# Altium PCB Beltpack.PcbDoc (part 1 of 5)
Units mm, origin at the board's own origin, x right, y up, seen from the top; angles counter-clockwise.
Board outline 85 x 81 mm, 4 copper layers (Top Layer, Inner-1, Inner_GND, Bottom Layer), stack 1.556 mm thick; 389 components, 291 nets, 1372 pads, 660 vias.
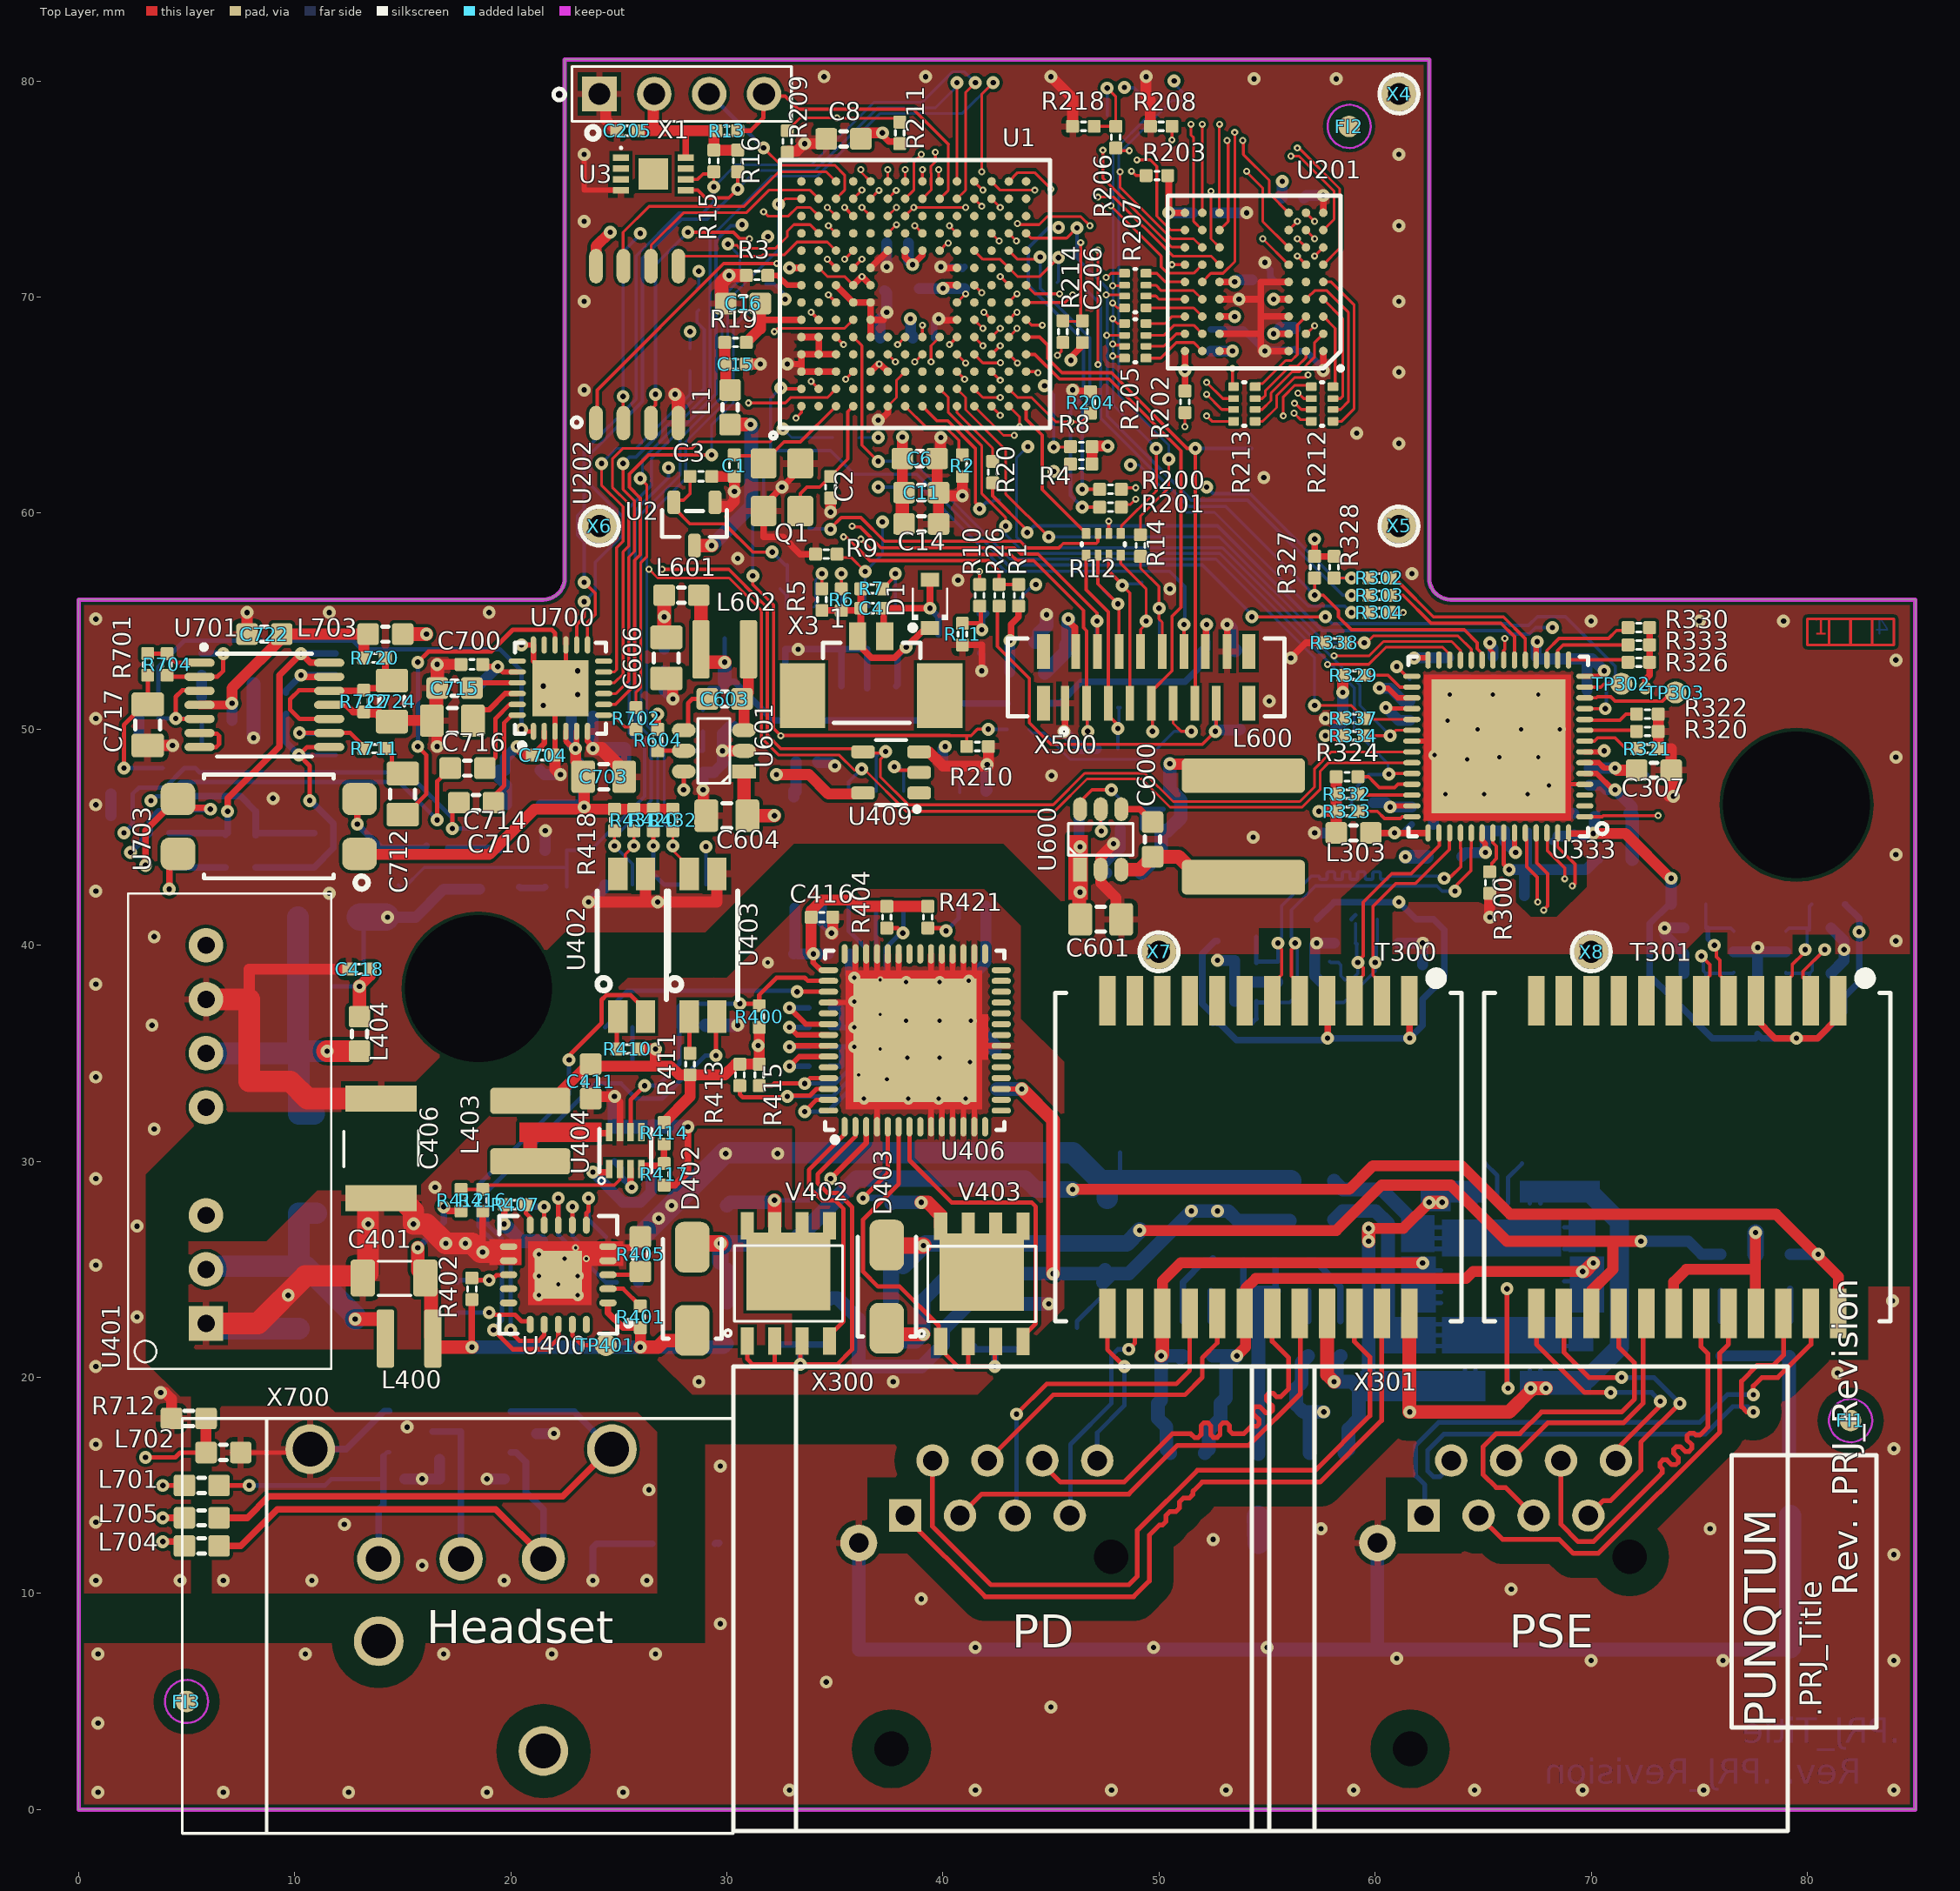
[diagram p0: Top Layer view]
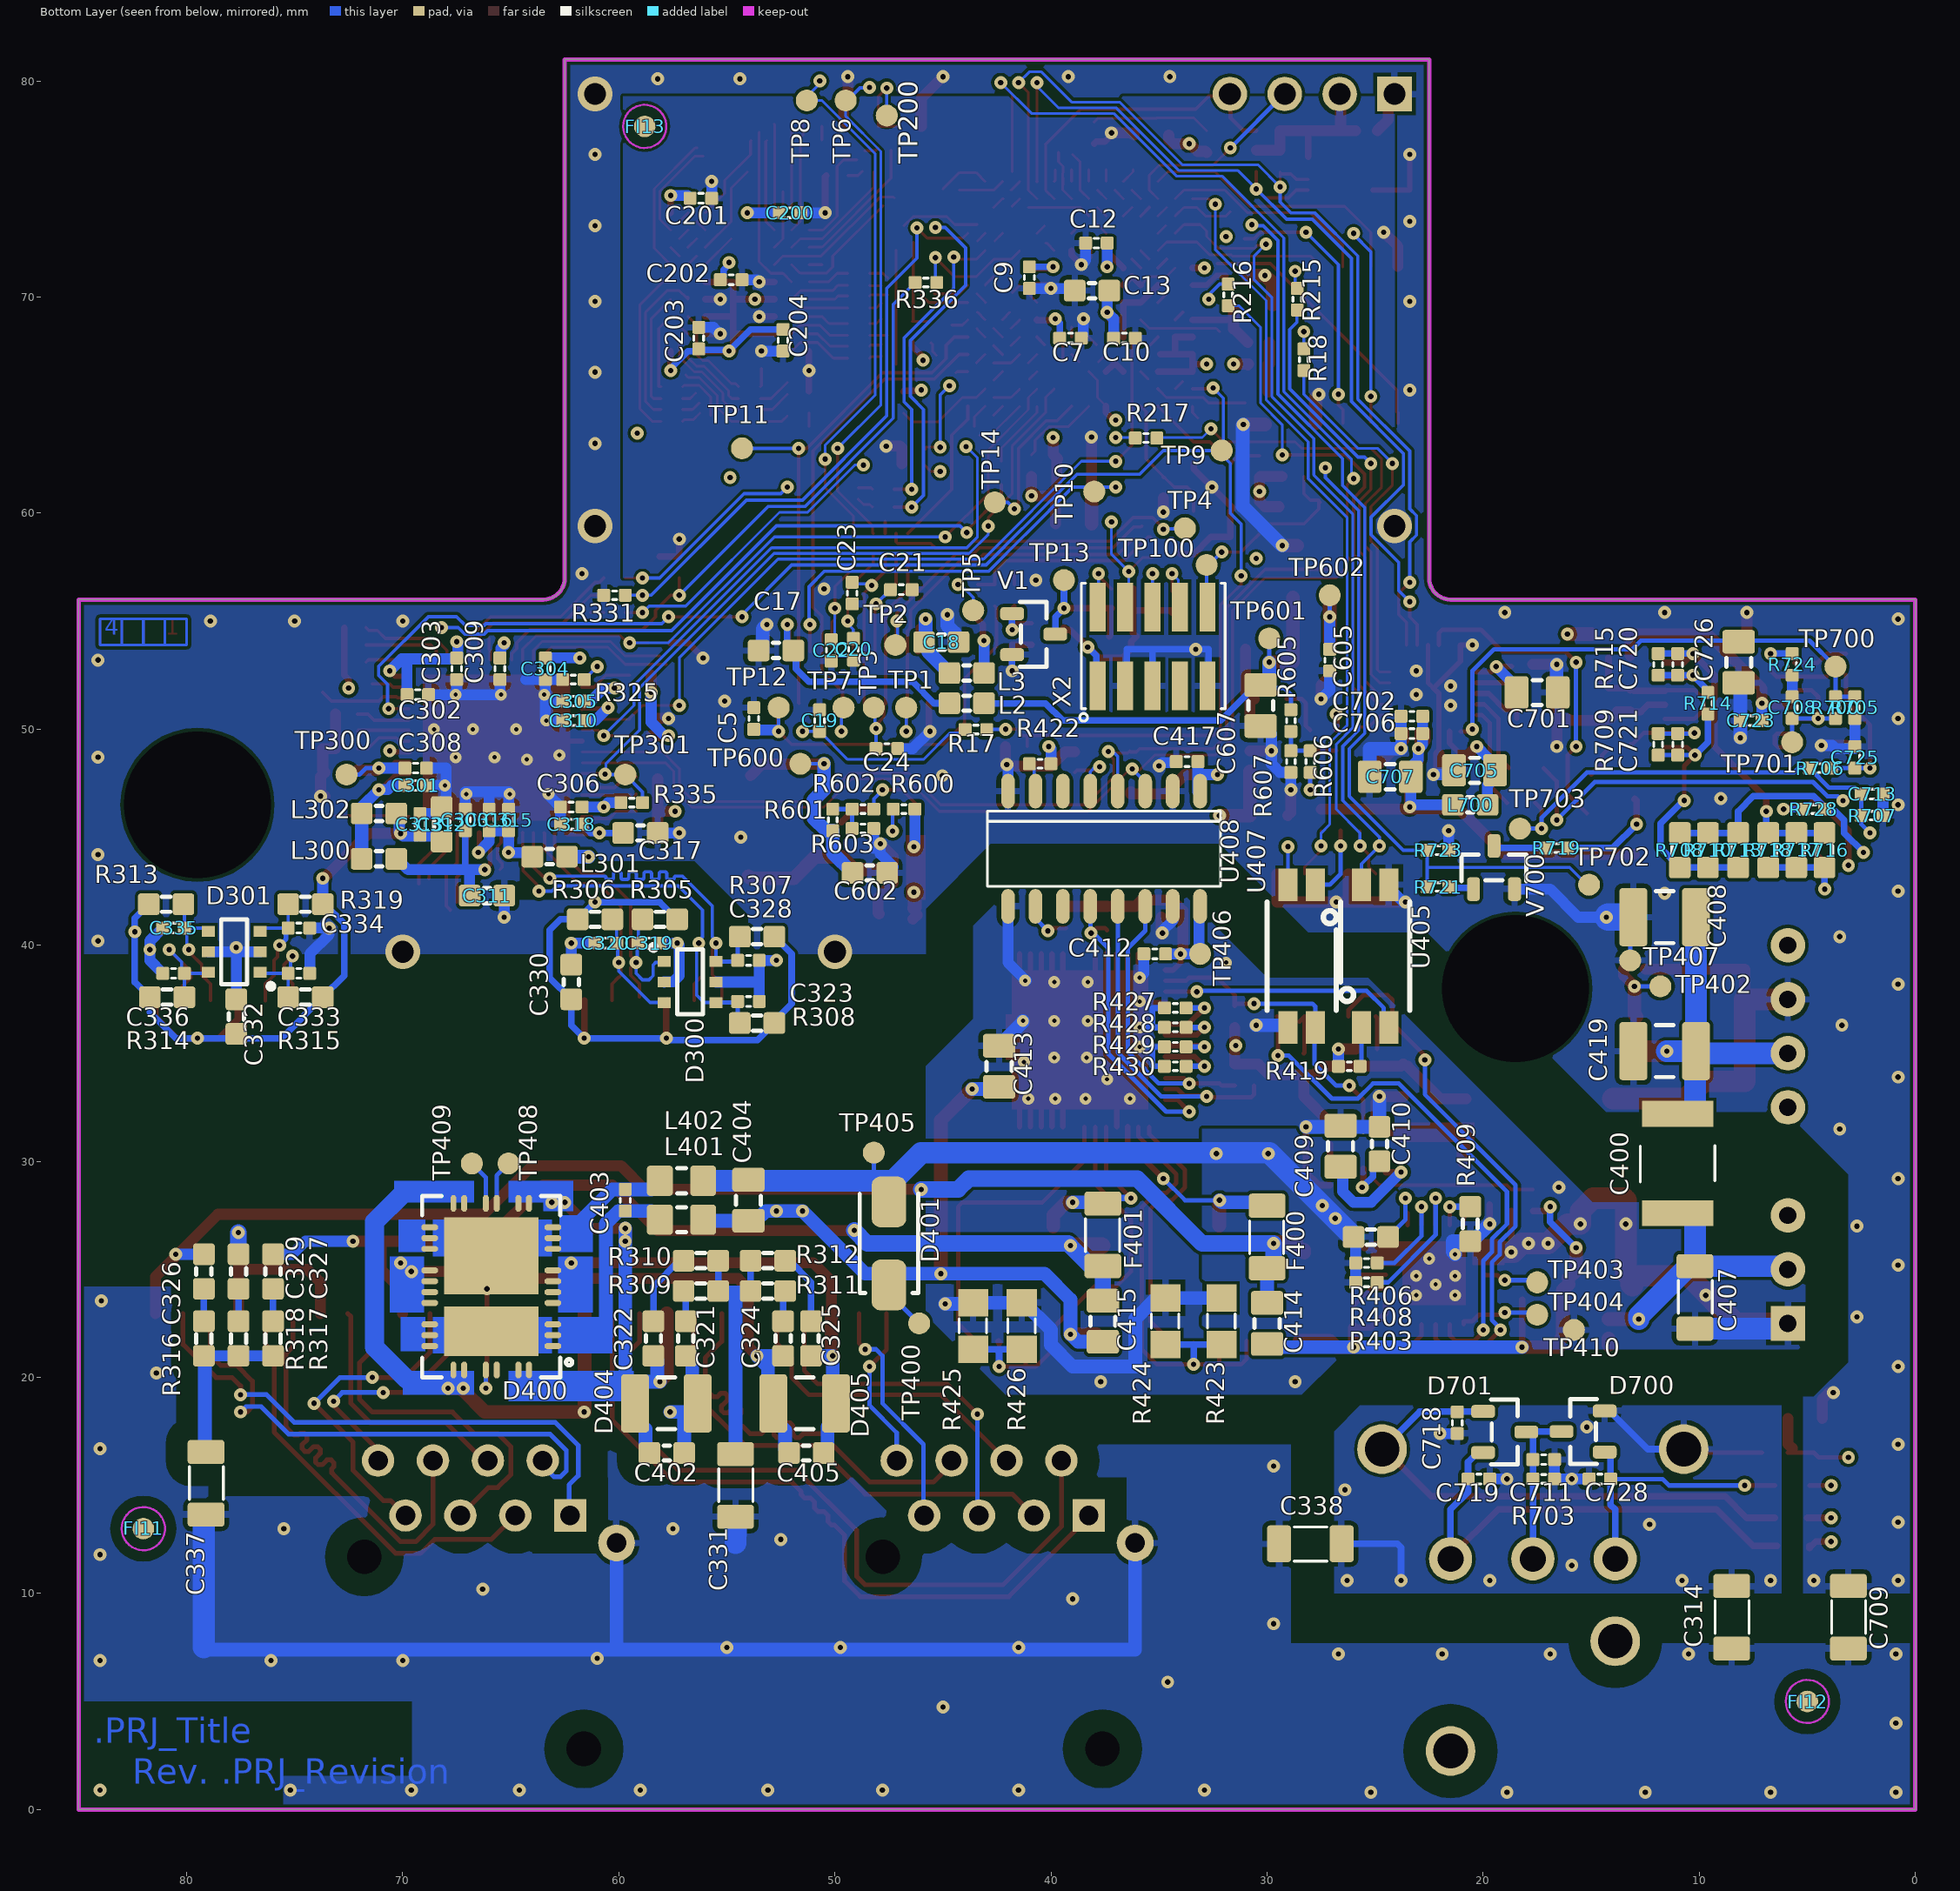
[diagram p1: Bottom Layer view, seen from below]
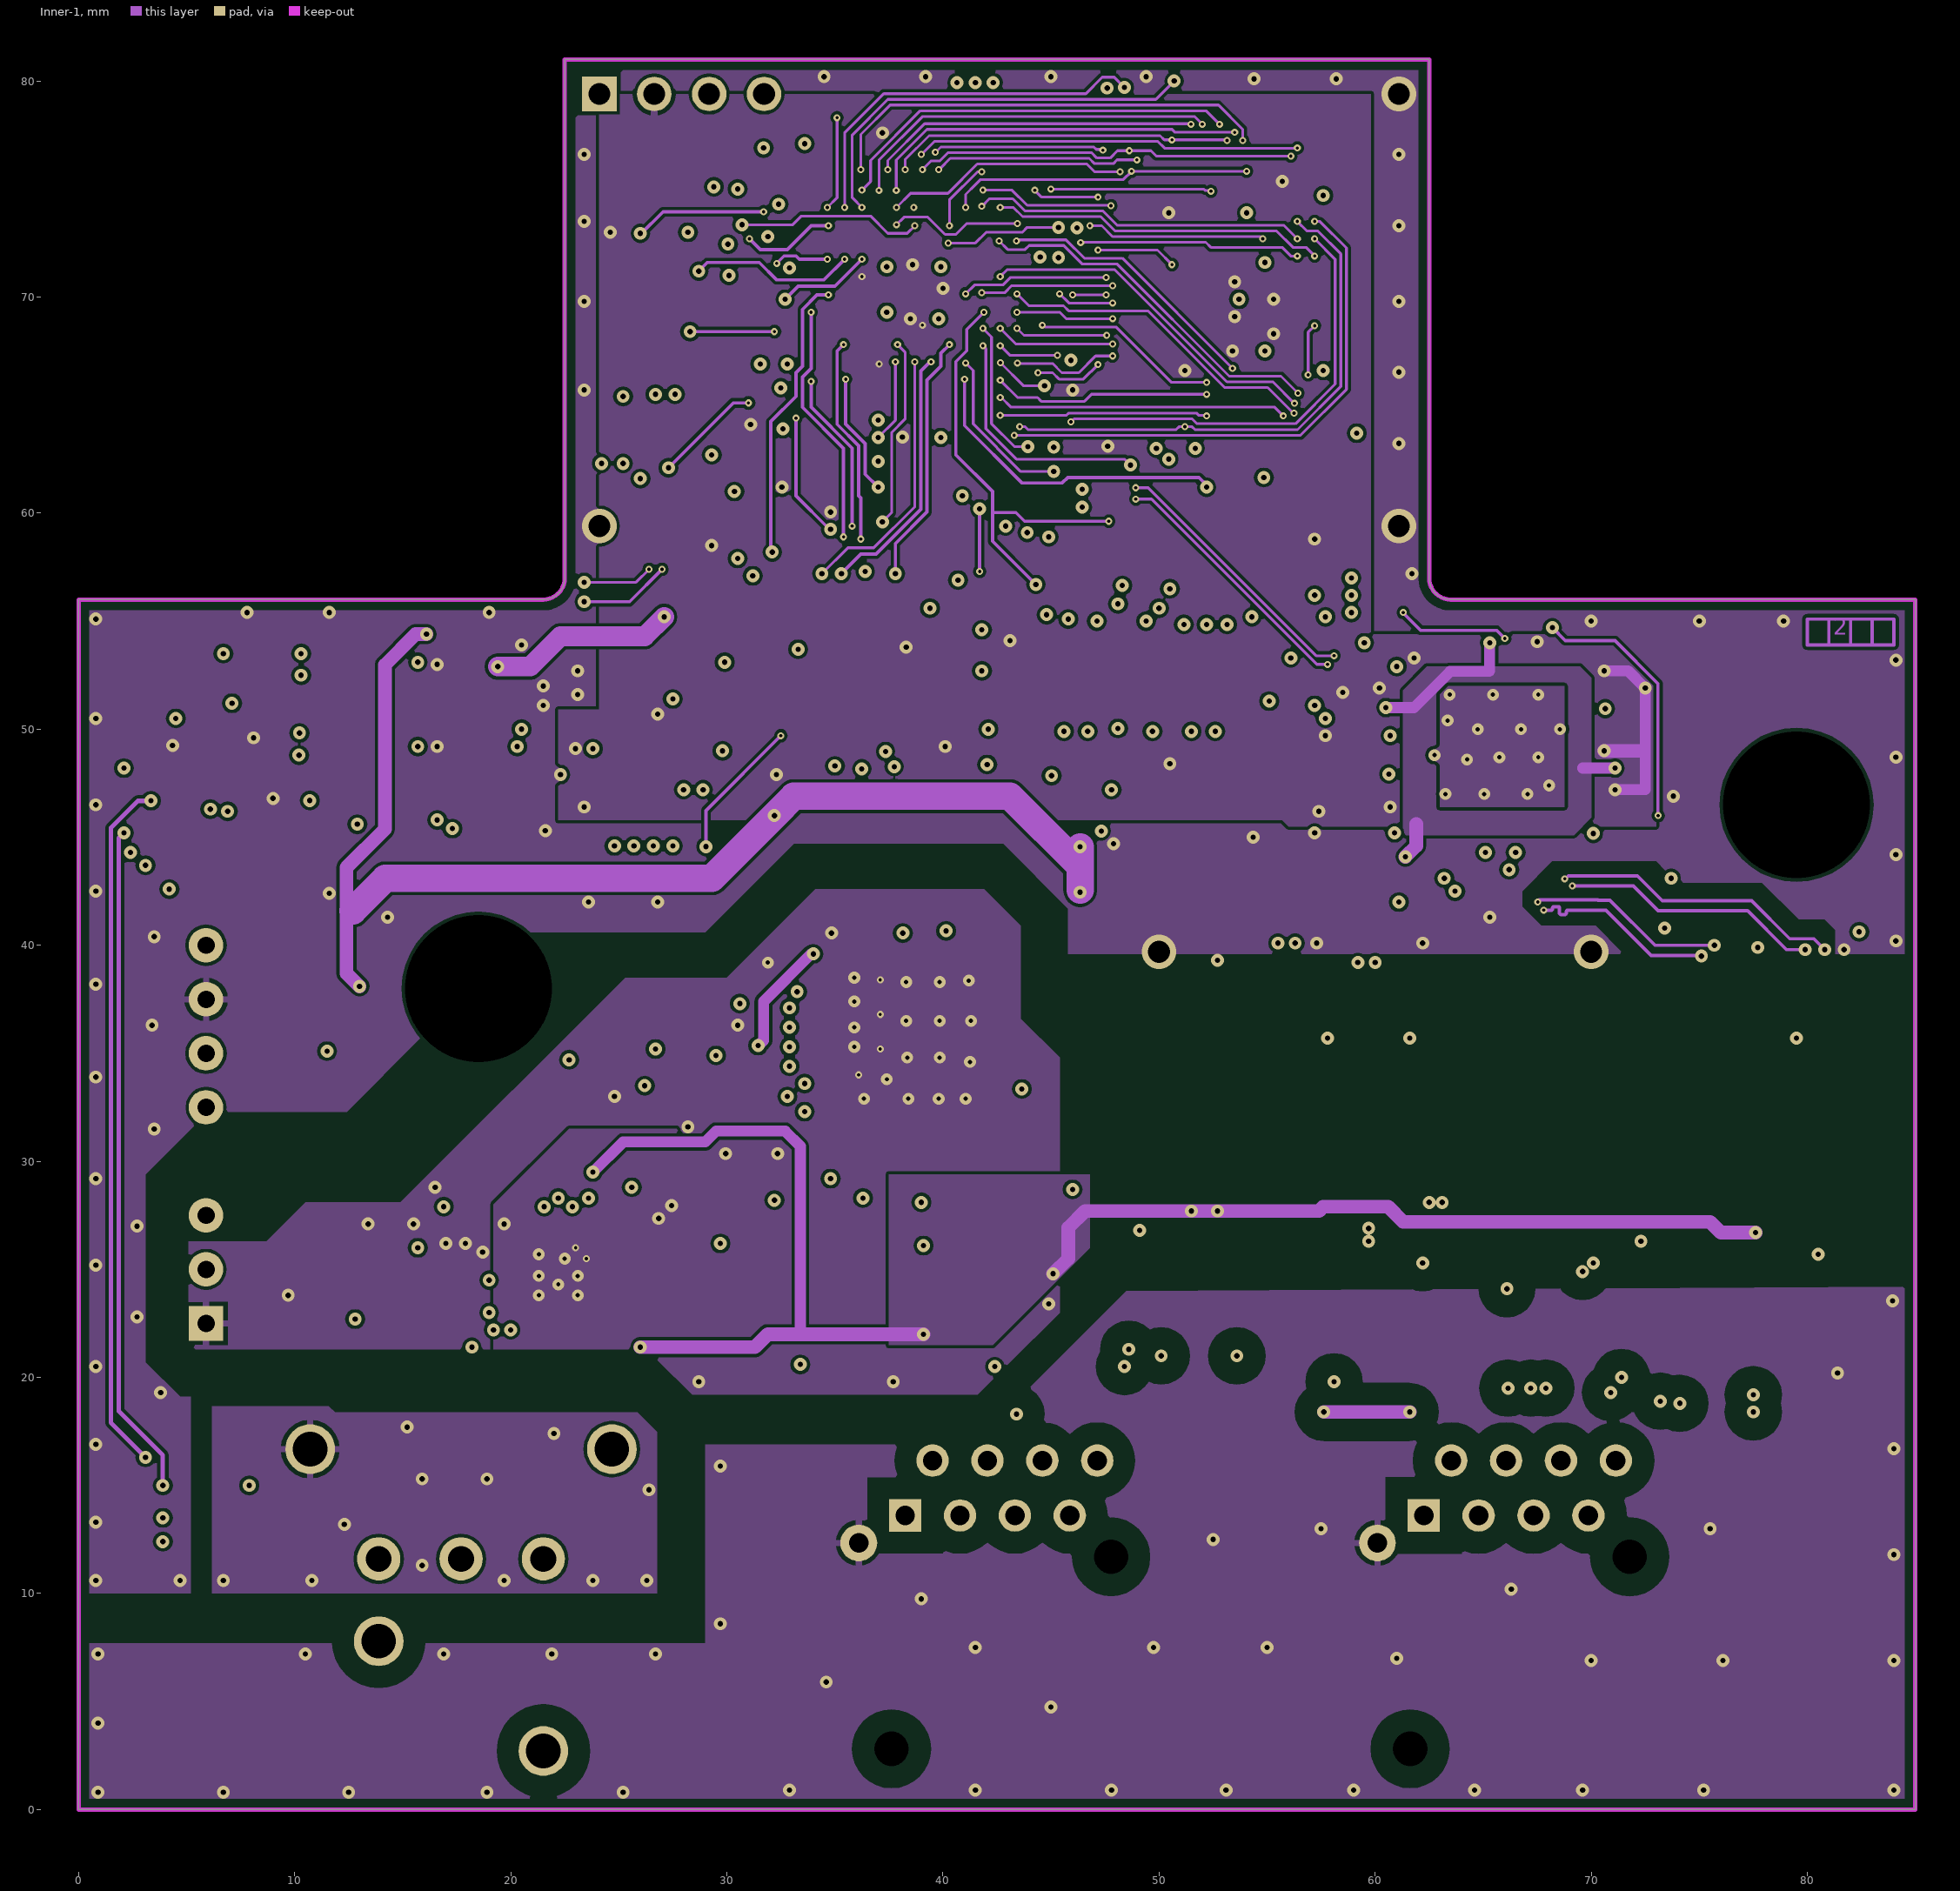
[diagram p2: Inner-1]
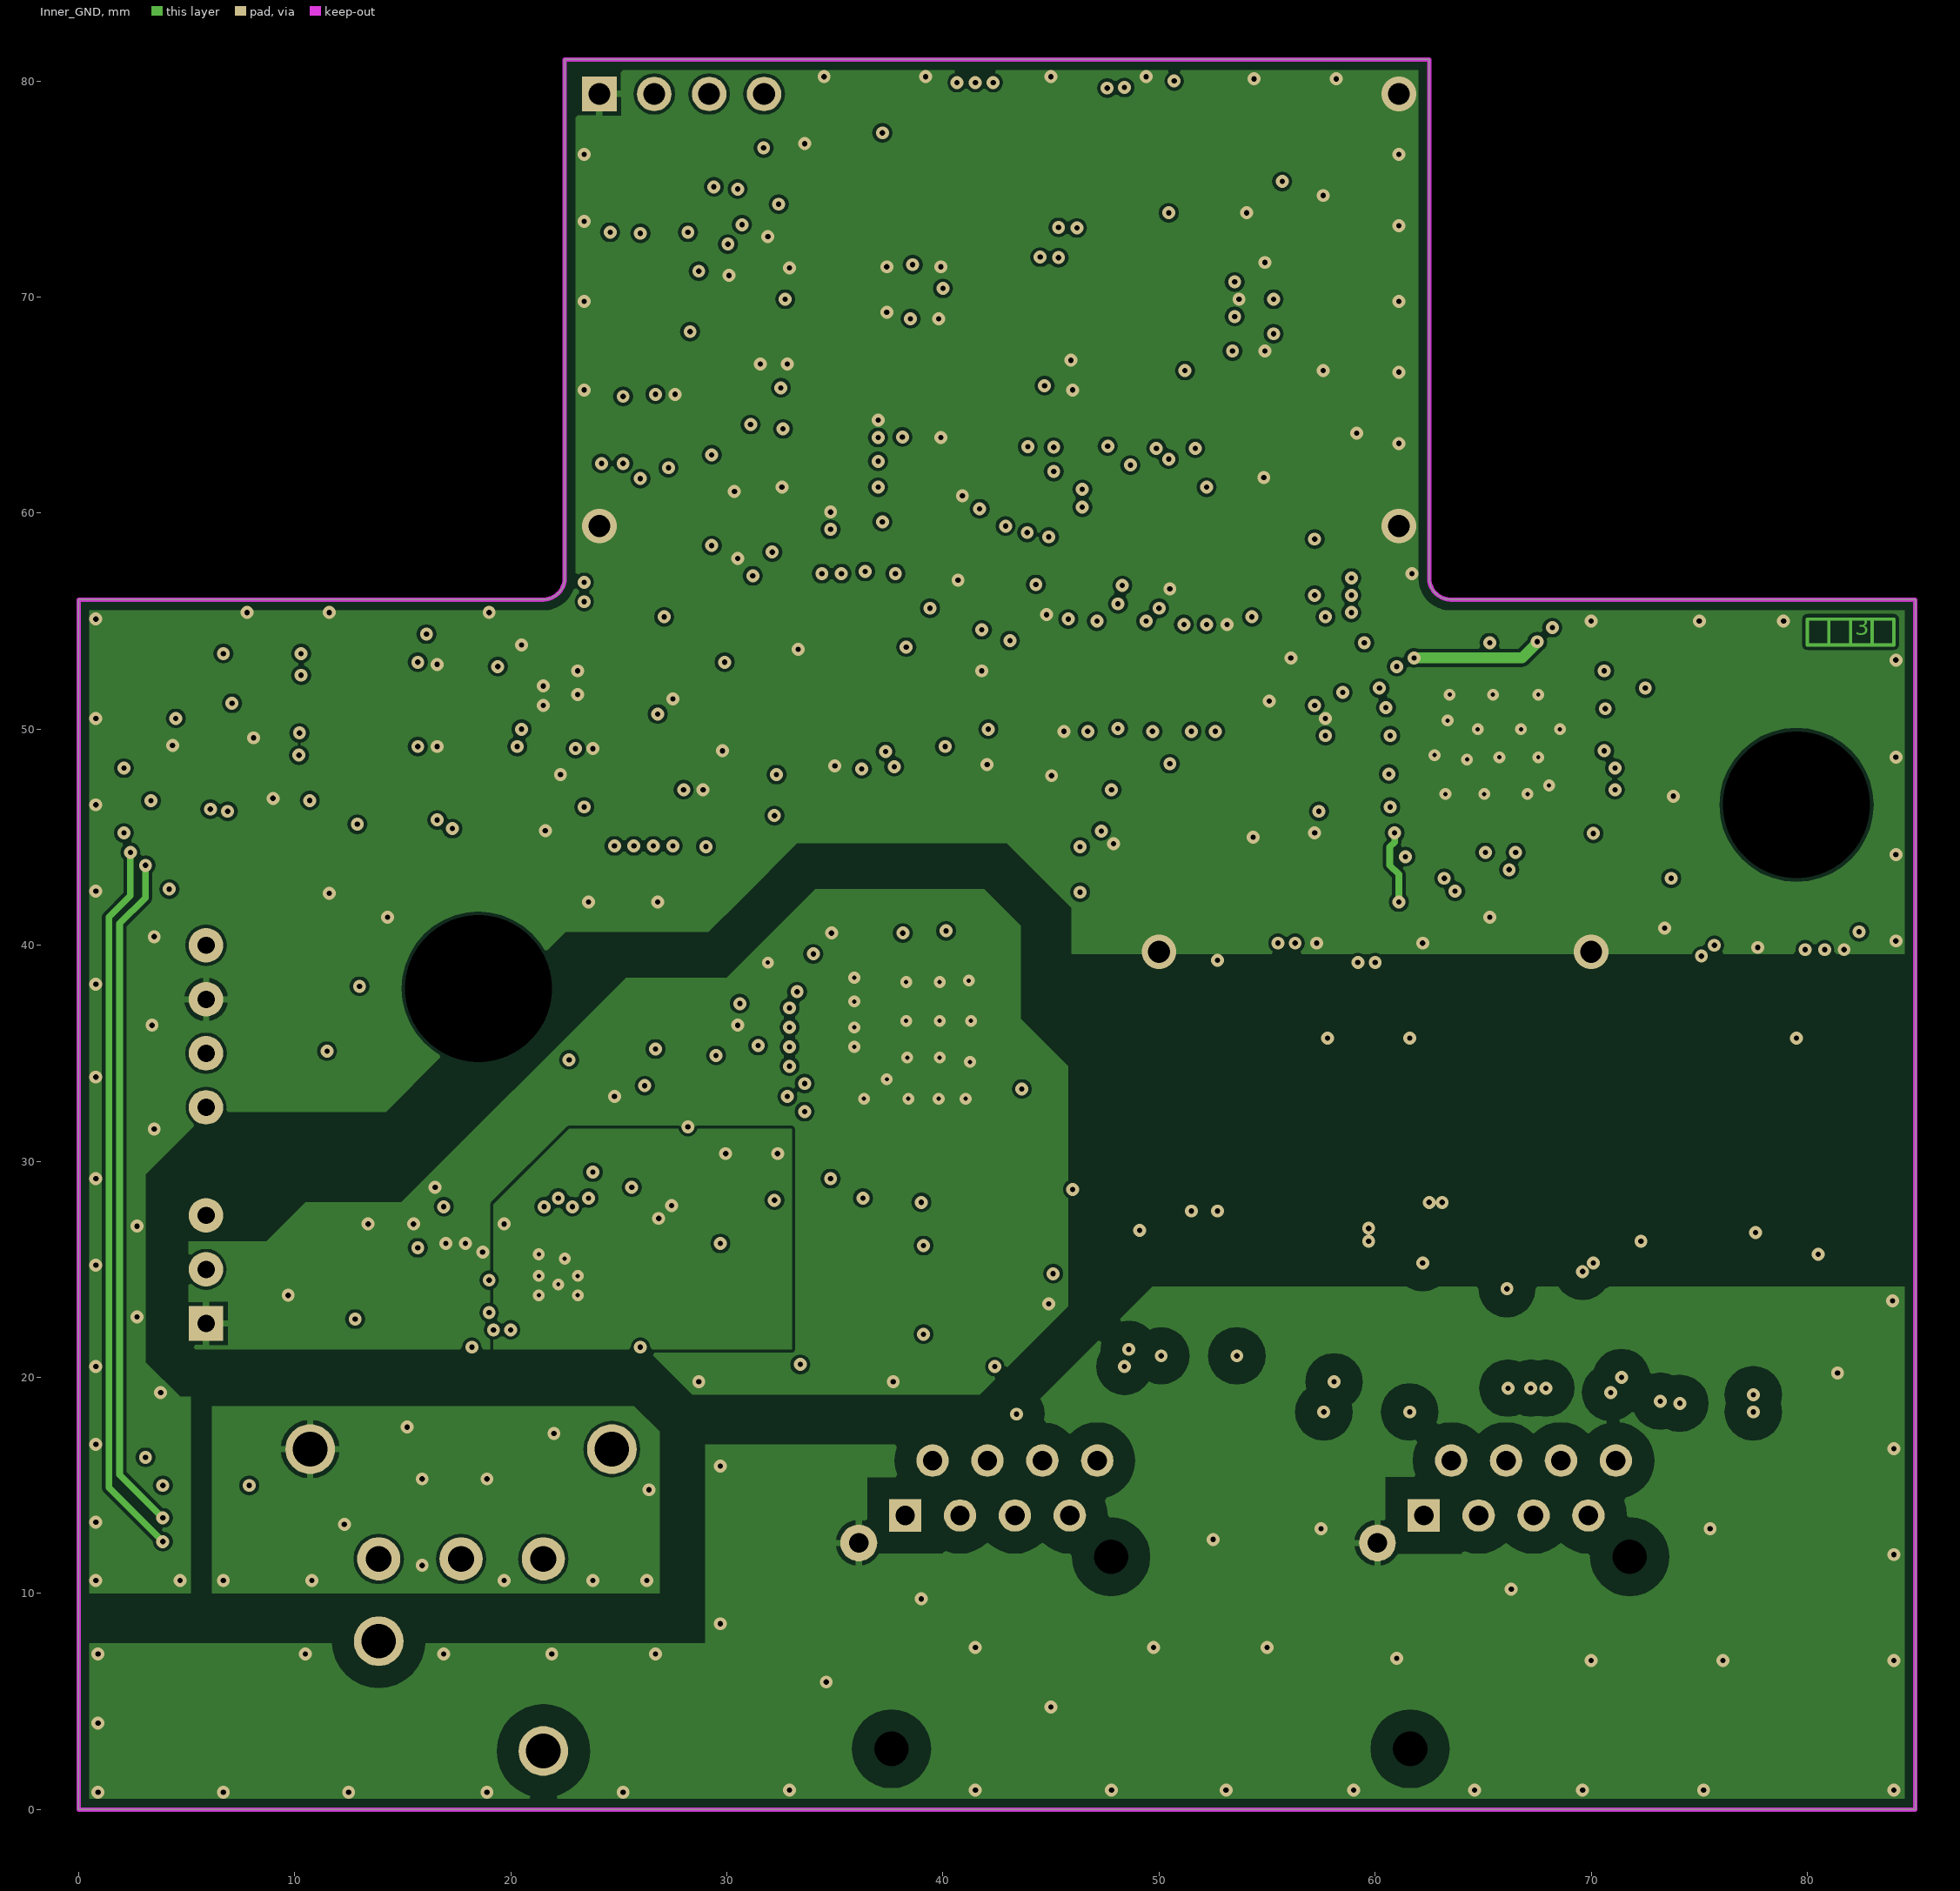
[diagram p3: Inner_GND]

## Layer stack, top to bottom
Top Solder: solder mask 0.017, Solder Resist, Dk 3.3
Top Layer: signal copper 0.035
Dielectric1: core 0.108, Dk 3.6
Inner-1: signal copper 0.035
Dielectric2: prepreg 1.2, FR-4, Dk 4.2
Inner_GND: signal copper 0.035
Dielectric 3: core 0.108, Dk 3.6
Bottom Layer: signal copper 0.035
Bottom Solder: solder mask 0.017, Solder Resist, Dk 3.3

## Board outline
0,0 0,56 21.5,56 ccw(c21.5,57) 22.5,57 22.5,81 62.5,81 62.5,57 ccw(c63.5,57) 63.5,56 85,56 85,0

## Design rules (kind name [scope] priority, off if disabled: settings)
AssemblyTestpoint [All] p1: testpointundercomponent=TRUE minsize=1 maxsize=2.54 preferedsize=1 minholesize=0 maxholesize=1 preferedholesize=0 testpointgrid=0.025 usegrid=FALSE gridtolerance=0 allowsidebottom=TRUE minspacing=2
BoardOutlineClearance BoardClearanceINNER [OnLayer('Inner-1')   OR OnLayer ('Inner_GND')] p1: gap=0.5 ignorepadtopadclearanceinfootprint=FALSE
Clearance Clearance_3V3MCU_TOP [InNamedPolygon('L4_3V3MCU')] p1: gap=0.127 ignorepadtopadclearanceinfootprint=FALSE except(0: Arc-Hole Track-Hole SMDPad-Hole THPad-Hole Via-Hole Fill-Hole Poly-Hole Region-Hole Text-Hole)
Clearance Clearance_GND_MCUTOP [InNamedPolygon('GND_MCUTOP')] p2: gap=0.15 ignorepadtopadclearanceinfootprint=FALSE
Clearance Clearance_3V3INNER [InNamedPolygon('3V3_INNER')] p3: gap=0.15 ignorepadtopadclearanceinfootprint=FALSE
Clearance Clearance_Earth [InNet('EARTH') vs Not IsBoardOutline And Not IsKeepOut] p4: gap=1.016 ignorepadtopadclearanceinfootprint=TRUE // Bob Smith plane
Clearance Clearance_Polygon [InPolygon] p5: gap=0.15 ignorepadtopadclearanceinfootprint=FALSE
Clearance Clearance_SolderPad [(InPadClass('Pad Class BoardEdge')) vs (IsBoardCutoutRegion)] p6: gap=0.508 ignorepadtopadclearanceinfootprint=FALSE except(0: Arc-Hole Track-Hole SMDPad-Hole THPad-Hole Via-Hole Fill-Hole Poly-Hole Region-Hole Text-Hole)
Clearance Clearance_DiffPair [(InDifferentialPairClass('All Differential Pairs'))] p7: gap=0.102 ignorepadtopadclearanceinfootprint=FALSE
Clearance [All] p8: gap=0.135 ignorepadtopadclearanceinfootprint=FALSE
ComponentClearance [All] p1: gap=0.2 collisioncheckmode=3 verticalgap=0.2 showdistances=FALSE
DiffPairsRouting ETH_Routing [All] p1: maxlimit=0.508 minlimit=0.152 mostfreqgap=0.305 toplayer_minwidth=0.127 toplayer_maxwidth=0.305 toplayer_prefwidth=0.152 midlayer1_minwidth=0.127 midlayer1_maxwidth=0.305 midlayer1_prefwidth=0.152 midlayer2_minwidth=0.127 midlayer2_maxwidth=0.305 midlayer2_prefwidth=0.152 bottomlayer_minwidth=0.127 bottomlayer_maxwidth=0.305 bottomlayer_prefwidth=0.152 maxuncoupledlength=12.7 // 100 Ohm diff pair (acc. to WE)
FabricationTestPointUsage TestPointUsage [All] p1: valid=0 allowmultiple=FALSE
FabricationTestpoint Testpoint [All] p1: side=3 testpointundercomponent=TRUE minsize=1 maxsize=2.54 preferedsize=1.524 minholesize=0 maxholesize=1 preferedholesize=0.813 testpointgrid=0.025 allowsidetop=TRUE allowsidebottom=TRUE usegrid=FALSE gridtolerance=0
HoleSize HoleSize_BigPad [(InPadClass('PadBig'))] p1: absolutevalues=TRUE maxlimit=25.4 minlimit=0.025 maxpercent=80.000 minpercent=20.000
HoleSize HoleSize_RJ45_Mountighole [(InPadClass('PAD_HOLE'))] p2: absolutevalues=FALSE maxlimit=0 minlimit=0 maxpercent=80.000 minpercent=-20.000
HoleSize [All] p3: absolutevalues=TRUE maxlimit=3.81 minlimit=0.15 maxpercent=80.000 minpercent=20.000
MinimumSolderMaskSliver [All] p1: minsoldermaskwidth=0.3
PlaneClearance [All] p1: clearance=0.203
PlaneConnect [All] p1: planeconnectstyle=Relief reliefexpansion=0.152 reliefentries=4 reliefconductorwidth=0.254 reliefairgap=0.152
PolygonConnect PolygonConnect_3V3_INNER [All vs IsNamedPolygon('3V3_INNER')] p1: connectstyle=Direct reliefconductorwidth=0.254 reliefentries=4 polygonreliefangle="90 Angle" airgapwidth=0.254
PolygonConnect PolygonConnect_Via [IsVia] p2: connectstyle=Direct reliefconductorwidth=0.254 reliefentries=4 polygonreliefangle="90 Angle" airgapwidth=0.254
PolygonConnect [All] p3: connectstyle=Relief reliefconductorwidth=0.305 reliefentries=4 polygonreliefangle="90 Angle" airgapwidth=0.203
RoutingVias [All] p1: holewidth=0.25 width=0.6 viastyle="Through Hole" minholewidth=0.15 minwidth=0.325 maxholewidth=0.711 maxwidth=1.27
SilkToSolderMaskClearance SilkscreenOverComponentPads [IsPad] p1: minsilkscreentomaskgap=0.254 clearancetoexposedcopper=TRUE
SolderMaskExpansion [All] p1: expansion=0
Width [All] p1: maxlimit=2.54 minlimit=0.127 preferedwidth=0.152 midlayer2_minwidth=0.152 minimp=50.000000 maximp=50.000000 favimp=50.000000
20 further rules are at their usual default settings.

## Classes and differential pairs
pad class PadBig: Free-HOLE1 Free-HOLE2
differential pair ETHOUT_T2: +ETHOUT_T2_P -ETHOUT_T2_N
differential pair ETHOUT_T1: +ETHOUT_T1_P -ETHOUT_T1_N
differential pair ETHIN_T2: +ETHIN_T2_P -ETHIN_T2_N
differential pair ETHIN_T1: +ETHIN_T1_P -ETHIN_T1_N
differential pair RXA: +RXA_P -RXA_N
differential pair RXB: +RXB_P -RXB_N
differential pair TXA: +TXA_P -TXA_N
differential pair TXB: +TXB_P -TXB_N

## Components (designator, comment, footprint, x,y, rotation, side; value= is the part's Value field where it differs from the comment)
C1 "15P" C0402 30.35,62.2 r270 top
C2 "15P" C0402 34.8,61.2 r270 top
C3 "220P" C0402 28.8,61.7 r180 top
C4 "100N" C0402 36.7,55.6 r0 top
C5 "220P" C0402 53.75,50.493 r270 bottom
C6 "4.7N" C0603 38.925,62.525 r0 top
C7 "100N" C0402 39.1,68.1 r0 bottom
C8 "4.7N" C0603 35.4,77.325 r180 top
C9 "100N" C0402 41,70.9 r90 bottom
C10 "100N" C0402 36.6,68.1 r0 bottom
C11 "1U" C0603 39,60.95 r0 top
C12 "100N" C0402 37.9,72.5 r180 bottom
C13 "4.7N" C0603 38.1,70.3 r180 bottom
C14 "22U" C0603 39,59.5 r0 top
C15 "100N" C0402 30.4,66.9 r0 top
C16 "1U" C0603 30.75,69.7 r180 top
C17 "1U" C0603 52.725,53.643 r180 bottom
C18 "1U" C0603 45.075,54.032 r0 bottom
C19 "220P" C0402 50.708,50.4 r270 bottom
C20 "47P" C0402 49.142,53.7 r90 bottom
C21 "47P" C0402 46.925,56.458 r0 bottom
C22 "47P" C0402 50.169,53.65 r90 bottom
C23 "47P" C0402 49.2,56.3 r90 bottom
C24 "47P" C0402 47.6,49.1 r0 bottom
C200 "100N" C0402 52.075,73.9 r0 bottom
C201 "100N" C0402 56.2,74.575 r0 bottom
C202 "100N" C0402 54.8,70.8 r0 bottom
C203 "100N" C0402 56.3,68.1 r270 bottom
C204 "100N" C0402 52.4,68 r90 bottom
C205 "100N" C0402 25.4,77.7 r180 top
C206 "10P" C0402 46.456,68.399 r90 top
C300 "100N" C0402 67.1,45.8 r90 bottom
C301 "100N" C0402 69.4,47.4 r180 bottom
C302 "100N" C0402 69.3,51.6 r180 bottom
C303 "100N" C0402 67.5,52.8 r270 bottom
C304 "100N" C0402 63.4,52.8 r270 bottom
C305 "100N" C0402 62.1,51.3 r0 bottom
C306 "100N" C0402 62.2,46.4 r0 bottom
C307 "1U" C0603 72.9,48.1 r0 top
C308 "100N" C0402 69.4,48.2 r180 bottom
C309 "100N" C0402 65.5,52.8 r270 bottom
C310 "220P" C0402 62.1,50.4 r180 bottom
C311 "1U" C0603 66.1,42.3 r180 bottom
C312 "1U" C0603 68.2,45.6 r90 bottom
C313 "100N" C0402 69.2,45.6 r90 bottom
C314 "1N" C1206 8.5,8.9 r270 bottom
C315 "100N" C0402 65.1,45.8 r90 bottom
C316 "100N" C0402 66,45.8 r90 bottom
C317 "1U" C0603 59,45.2 r180 bottom
C318 "100N" C0402 62.2,45.6 r0 bottom
C319 "10P" C0402 58.6,40.1 r180 bottom
C320 "10P" C0402 60.6,40.1 r0 bottom
C321 "10N" C0603 56.9,21.8 r90 bottom
C322 "10N" C0603 58.4,21.8 r90 bottom
C323 "10P" C0402 54,37.4 r180 bottom
C324 "10N" C0603 52.4,21.8 r90 bottom
C325 "10N" C0603 51.1,21.8 r90 bottom
C326 "10N" C0603 79.2,24.9 r270 bottom
C327 "10N" C0603 76,24.9 r270 bottom
C328 "10P" C0402 54,39.3 r180 bottom
C329 "10N" C0603 77.6,24.9 r270 bottom
C330 "22N" C0603 62.2,38.3 r270 bottom
C331 "1N" C1206 54.6,15 r270 bottom
C332 "22N" C0603 77.7,36.7 r270 bottom
C333 "10P" C0402 74.8,38.7 r180 bottom
C334 "10P" C0402 74.8,40.8 r180 bottom
C335 "10P" C0402 80.6,40.8 r0 bottom
C336 "10P" C0402 80.6,38.7 r0 bottom
C337 "1N" C1206 79.1,15.1 r270 bottom
C338 "1N" C1206 28,12.3 r0 bottom
C400 "1N5" C1812 11,29.9 r90 bottom
C401 "2U2" C1206 14.6,24.6 r180 top
C402 "10N" C0603 57.778,16.5 r0 bottom
C403 "1N" C0402 59.7,28.2 r90 bottom
C404 "100N" C0805 54,28.2 r90 bottom
C405 "10N" C0603 51.319,16.5 r180 bottom
C406 "1N5" C1812 14,30.6 r90 top
C407 "2U2" C1206 10.2,23.7 r270 bottom
C408 "47U" C1210 11.6,41.3 r0 bottom
C409 "1U" C0805 26.6,30.7 r90 bottom
C410 "1U" C0603 24.8,30.8 r90 bottom
C411 "22U" C0603 23.7,33.7 r270 top
C412 "100N" C0402 35.2,39.6 r180 bottom
C413 "100N" C0805 42.4,34.4 r90 bottom
C414 "100N" C0805 30,22.5 r90 bottom
C415 "100N" C0805 37.6,22.6 r90 bottom
C416 "100N" C0402 34.4,41.3 r180 top
C417 "100N" C0402 33.7,48.5 r180 bottom
C418 "100N" C0402 13,38.9 r180 top
C419 "47U" C1210 11.6,35.1 r0 bottom
C600 "1U" C0603 49.7,44.9 r270 top
C601 "22U" C0805 47.3,41.2 r0 top
C602 "22U" C0603 48.38,43.351 r180 bottom
C603 "1U" C0603 29.9,51.4 r0 top
C604 "22U" C0805 30,46 r180 top
C605 "100N" C0402 27.1,53.2 r90 bottom
C606 "4.7U" C0805 27.2,53.3 r90 top
C607 "22U" C0805 30.3,51.1 r270 bottom
C700 "100N" C0402 18.2,53 r0 top
C701 "4.7U" C0805 17.5,51.7 r0 bottom
C702 "100N" C0402 23.3,50.6 r180 bottom
C703 "4.7U" C0805 24.3,47.8 r180 top
C704 "100N" C0402 21.5,48.8 r180 top
C705 "4.7U" C0805 20.4,48.1 r180 bottom
C706 "100N" C0402 23.3,49.8 r180 bottom
C707 "4.7U" C0805 24.3,47.8 r180 bottom
C708 "100N" C0402 5.7,51 r270 bottom
C709 "1N" C1206 3.1,8.9 r270 bottom
C710 "1U" C0603 18.4,46.6 r0 top
C711 "100N" C0402 17.2,16.2 r180 bottom
C712 "4.7U" C0805 15,47 r90 top
C713 "220P" C0402 2,47 r0 bottom
C714 "1U" C0603 18,48.2 r0 top
C715 "1U" C0603 17.4,51.9 r0 top
C716 "4.7U" C0805 17.3,50.4 r180 top
C717 "2.2U" C0805 3.2,50.2 r270 top
C718 "47P" C0402 21.2,17.9 r270 bottom
C719 "47P" C0402 20.2,15.3 r180 bottom
C720 "47P" C0402 11,53 r270 bottom
C721 "47P" C0402 11,49.3 r90 bottom
C722 "1U" C0603 8.6,54.4 r0 top
C723 "100N" C0402 7.6,50.4 r180 bottom
C724 "22U" C0805 14.5,51.3 r90 top
C725 "100N" C0402 2.8,48.7 r270 bottom
C726 "4.7U" C0805 8.176,53.096 r90 bottom
C728 "47P" C0402 14.6,15.3 r180 bottom
D1 "1N4148" SOD323 39.4,55.8 r90 top
D300 "TVS3V3L4U" SC74-6-2 56.7,38.3 r180 bottom value=RClamp0502B
D301 "TVS3V3L4U" SC74-6-2 77.8,39.7 r0 bottom value=RClamp0502B
D400 "PD70224" PD70224 65.9,24.2 r0 bottom
D401 "SMAJ58A" DO214AC 47.5,26.2 r90 bottom
D402 "SMAJ58A" DO214AC 28.4,24.1 r90 top
D403 "SMAJ58A" DO214AC 37.4,24.2 r90 top
D404 "VC121060J121DP" C1210 57.8,18.8 r0 bottom
D405 "VC121060J121DP" C1210 51.4,18.8 r180 bottom
D700 "PESD24VL2BT" SOT23 15.376,17.496 r90 bottom
D701 "PESD24VL2BT" SOT23 19.004,17.476 r270 bottom
F400 "1.5A" C1206 30,26.5 r90 bottom
F401 "1.5A" C1206 37.6,26.6 r90 bottom
FI1 "FIDUCIAL" FIDUCIAL_1MM 82,18 r0 top
FI2 "FIDUCIAL" FIDUCIAL_1MM 58.8,77.9 r0 top
FI3 "FIDUCIAL" FIDUCIAL_1MM 5,5 r0 top
FI11 "FIDUCIAL" FIDUCIAL_1MM 82,13 r90 bottom
FI12 "FIDUCIAL" FIDUCIAL_1MM 5,5 r90 bottom
FI13 "FIDUCIAL" FIDUCIAL_1MM 58.8,77.9 r90 bottom
L1 "330R" L0603 30.15,64.9 r270 top
L2 "330R" L0603 43.9,51.2 r180 bottom
L3 "330R" L0603 43.9,52.6 r180 bottom
L300 "330R" L0603 71.1,44 r180 bottom
L301 "330R" L0603 63.2,44.1 r0 bottom
L302 "330R" L0603 71.1,46.1 r180 bottom
L303 "330R" L0603 59,45.2 r0 top
L400 "10 uH" L_NR3015 15.3,21.8 r180 top
L401 "600Ohm@100MHz" L0805 57.1,27.3 r180 bottom value=MPZ2012S601AT000
L402 "600Ohm@100MHz" L0805 57.1,29.1 r180 bottom value=MPZ2012S601AT000
L403 "33 uH" L_NR4018 20.9,31.4 r90 top
L404 "330R" L0603 13,35.9 r270 top
L600 "22 uH" L_NR6028 53.9,45.5 r90 top
L601 "330R" L0603 27.9,56.2 r0 top
L602 "22 uH" L_NR3015 29.9,53.7 r180 top
L700 "330R" L0603 20.6,46.5 r0 bottom
L701 "330R" L0603 5.7,15 r180 top
L702 "330R" L0603 6.704,16.524 r180 top
L703 "330R" L0603 14.2,54.4 r180 top
L704 "330R" L0603 5.7,12.2 r180 top
L705 "330R" L0603 5.7,13.5 r180 top
Q1 "12.000MHz" Q_4PIN_3225 32.55,61.2 r270 top
R1 "4K7" R0402 43.5,56.2 r90 top
R2 "12K1" R0402 40.9,62.2 r90 top
R3 "10K" R0402 31.4,71 r180 top
R4 "10K" R0402 46.4,62.275 r0 top
R5 "10K" R0402 34.4,56 r270 top
R6 "10K" R0402 35.3,56 r270 top
R7 "10K" R0402 36.7,56.5 r180 top
R8 "10K" R0402 46.4,63.075 r0 top
R9 "10K" R0402 34.6,58.1 r180 top
R10 "1K" R0402 41.7,56.2 r270 top
R11 "10K" R0402 40.9,54.4 r270 top
R12 "33R" R_0402X8_CONCAVE 47.425,58.559 r180 top
R13 "10K" R0402 30,77.7 r0 top
R14 "33R" R0402 49.141,58.5 r270 top
R15 "4K7" R0402 29.4,76.3 r270 top
R16 "4K7" R0402 30.5,76.3 r270 top
R17 "33R" R0402 43.475,49.983 r0 bottom
R18 "47R" R0402 28.3,67.1 r270 bottom
R19 "47R" R0402 30.4,67.9 r0 top
R20 "33R" R0402 42.3,61.9 r270 top
R26 "1K" R0402 42.6,56.2 r90 top
R200 "33R" R0402 47.75,61.1 r0 top
R201 "33R" R0402 47.75,60.275 r0 top
R202 "10K" R0402 51.2,65.15 r90 top
R203 "10K" R0402 49.9,75.625 r0 top
R204 "10K" R0402 46.825,65.125 r90 top
R205 "33R" R_0402X8_CONCAVE 48.9,67.975 r90 top
R206 "10K" R0402 48,77.4 r90 top
R207 "33R" R_0402X8_CONCAVE 48.9,70.3 r90 top
R208 "10K" R0402 50.1,77.9 r180 top
R209 "10K" R0402 32.8,77.2 r90 top
R210 "10K" R0402 41.6,49.2 r0 top
R211 "10K" R0402 38,77.6 r270 top
R212 "33R" R_0402X8_CONCAVE 57.55,65.05 r90 top
R213 "33R" R_0402X8_CONCAVE 53.95,65.05 r90 top
R214 "33R" R0402 45.55,68.4 r270 top
R215 "47R" R0402 28.6,69.9 r270 bottom
R216 "47R" R0402 31.8,70.1 r270 bottom
R217 "47R" R0402 35.604,63.476 r180 bottom
R218 "10K" R0402 46.5,77.9 r180 top
R300 "12K1" R0402 65.3,42.9 r90 top
R302 "33R" R0402 60.2,57 r0 top
R303 "33R" R0402 60.2,56.2 r0 top
R304 "33R" R0402 60.2,55.4 r0 top
R305 "49R9" R0603 58.1,41.2 r0 bottom
R306 "49R9" R0603 61.1,41.2 r180 bottom
R307 "49R9" R0603 53.6,40.4 r0 bottom
R308 "49R9" R0603 53.6,36.4 r0 bottom
R309 "75R" R0603 56.2,24 r0 bottom
R310 "75R" R0603 56.2,25.4 r0 bottom
R311 "75R" R0603 53.1,24 r180 bottom
R312 "75R" R0603 53.1,25.4 r180 bottom
R313 "49R9" R0603 80.95,41.9 r180 bottom
R314 "49R9" R0603 80.9,37.6 r180 bottom
R315 "49R9" R0603 74.5,37.6 r0 bottom
R316 "75R" R0603 79.2,21.8 r90 bottom
R317 "75R" R0603 76,21.8 r90 bottom
R318 "75R" R0603 77.6,21.8 r90 bottom
R319 "49R9" R0603 74.5,41.9 r0 bottom
R320 "10K" R0402 72.6,49.9 r0 top
R321 "10K" R0402 72.6,49.1 r180 top
R322 "10K" R0402 72.6,50.7 r0 top
R323 "10K" R0402 58.7,46.2 r0 top
R324 "10K" R0402 58.7,47.8 r0 top
R325 "10K" R0402 62.1,52.3 r180 bottom
R326 "10K" R0402 72.2,53.1 r180 top
R327 "10K" R0402 57.2,57.5 r90 top
R328 "10K" R0402 58.1,57.5 r90 top
R329 "10K" R0402 59,52.5 r180 top
R330 "10K" R0402 72.2,54.7 r0 top
R331 "10K" R0402 60.2,56.2 r0 bottom
R332 "10K" R0402 58.7,47 r0 top
R333 "10K" R0402 72.2,53.9 r180 top
R334 "1K" R0402 59,49.7 r180 top
R335 "10K" R0402 59.4,46.6 r0 bottom
R336 "33R" R0402 45.79,70.675 r0 bottom
R337 "10K" R0402 59,50.5 r0 top
R338 "10K" R0402 58.1,54 r0 top
R400 "4K7" R0402 31.5,36.7 r90 top
R401 "24K9" R0402 26,22.8 r90 top
R402 "47K" R0402 18.2,24.1 r270 top
R403 "1K3" R0402 25.4,24.4 r180 bottom
R404 "4K7" R0402 37.4,41.3 r270 top
R405 "63R4" R0603 26,25.7 r270 top
R406 "90R9" R0603 25.2,26.5 r180 bottom
R407 "0R" R0402 20.2,28 r0 top
R408 "49K9" R0402 25.4,25.3 r0 bottom
R409 "62K" R0603 20.6,27.1 r270 bottom
R410 "1K" R0402 25.4,35.2 r180 top
R411 "1K" R0402 28.3,34.5 r90 top
R412 "120K" R0402 17.7,28.2 r270 top
R413 "4K7" R0402 30.6,34 r270 top
R414 "150K" R0402 27.1,31.3 r270 top
R415 "4K7" R0402 31.5,34 r270 top
R416 "5K6" R0402 18.7,28.2 r90 top
R417 "56K" R0402 27.1,29.4 r270 top
R418 "10K" R0402 24.8,45.8 r270 top
R419 "1K" R0402 26.2,34.4 r180 bottom
R420 "1K" R0402 26.6,45.8 r90 top
R421 "1K" R0402 39.3,41.3 r90 top
R422 "1K" R0402 40.5,48.4 r180 bottom
R423 "0R51" R0805 32.1,22.6 r90 bottom
R424 "0R51" R0805 34.7,22.6 r90 bottom
R425 "0R51" R0805 43.6,22.373 r90 bottom
R426 "0R51" R0805 41.35,22.373 r90 bottom
R427 "1K" R0402 34.25,37.1 r180 bottom
R428 "1K" R0402 34.25,36.2 r180 bottom
R429 "1K" R0402 34.25,35.3 r180 bottom
R430 "1K" R0402 34.25,34.4 r180 bottom
R431 "10K" R0402 25.7,45.8 r270 top
R432 "10K" R0402 27.5,45.8 r270 top
R600 "100K" R0402 46.8,46.3 r0 bottom
R601 "47K" R0402 50.1,45.8 r90 bottom
R602 "47K" R0402 48.7,46.3 r0 bottom
R603 "15K" R0402 48.7,45.4 r180 bottom
R604 "47K" R0402 26.8,49.5 r90 top
R605 "36K" R0402 28.9,50.4 r270 bottom
R606 "47K" R0402 28,48.5 r90 bottom
R607 "6K8" R0402 28.9,48.5 r270 bottom
R700 "10K" R0402 3.7,51 r90 bottom
R701 "270R" R0402 3.2,53 r270 top
R702 "47R" R0402 25.8,50.5 r90 top
R703 "10K" R0402 17.2,15.3 r180 bottom
R704 "10K" R0402 4.1,53 r270 top
R705 "47K" R0402 2.8,51 r270 bottom
R706 "2K2" R0402 4.4,48.2 r180 bottom
R707 "47K" R0402 2,46 r180 bottom
R708 "39R" R0603 10.9,44.4 r270 bottom
R709 "47K" R0402 11.9,49.3 r90 bottom
R710 "39R" R0603 9.6,44.4 r270 bottom
R711 "15K" R0402 13.7,49.1 r0 top
R712 "0R" R0603 5.1,18.1 r0 top
R713 "39R" R0603 8.2,44.4 r270 bottom
R714 "36K" R0402 9.6,51.2 r270 bottom
R715 "36K" R0402 11.9,53 r270 bottom
R716 "39R" R0603 4.208,44.4 r90 bottom
R717 "39R" R0603 5.508,44.4 r90 bottom
R718 "39R" R0603 6.808,44.4 r90 bottom
R719 "270R" R0402 16.6,44.5 r180 bottom
R720 "10K" R0402 13.7,53.3 r0 top
R721 "10K" R0402 22.087,42.7 r180 bottom
R722 "10K" R0402 13.2,51.3 r270 top
R723 "10K" R0402 22.087,44.4 r180 bottom
R724 "10K" R0402 5.7,53 r270 bottom
R728 "47K" R0402 4.7,46.3 r0 bottom
T300 "T_ETH_7490220122" T_ETH_18.3x16.0MM 54.6,30.2 r180 top locked value=7490220122
T301 "T_ETH_7490220122" T_ETH_18.3x16.0MM 74.45,30.2 r180 top locked value=7490220122
TP1 "*" TP_SMD_1.0mm 46.7,51 r90 bottom
TP2 "*" TP_SMD_1.0mm 47.2,53.9 r90 bottom
TP3 "*" TP_SMD_1.0mm 48.2,51 r90 bottom
TP4 "*" TP_SMD_1.0mm 33.8,59.3 r90 bottom
TP5 "*" TP_SMD_1.0mm 43.6,55.5 r90 bottom
TP6 "*" TP_SMD_1.0mm 49.5,79.1 r90 bottom locked
TP7 "*" TP_SMD_1.0mm 49.6,51 r90 bottom
TP8 "*" TP_SMD_1.0mm 51.3,79.1 r90 bottom locked
TP9 "*" TP_SMD_1.0mm 32.1,62.9 r90 bottom
TP10 "*" TP_SMD_1.0mm 38,61 r90 bottom
TP11 "*" TP_SMD_1.0mm 54.3,63 r90 bottom locked
TP12 "*" TP_SMD_1.0mm 52.6,51 r90 bottom
TP13 "" TP_SMD_1.0mm 39.4,56.9 r90 bottom
TP14 "" TP_SMD_1.0mm 42.6,60.5 r90 bottom
TP100 "" TP_SMD_1.0mm 32.8,57.6 r90 bottom
TP200 "" TP_SMD_1.0mm 47.6,78.4 r90 bottom locked
TP300 "" TP_SMD_1.0mm 72.6,47.9 r90 bottom
TP301 "" TP_SMD_1.0mm 59.7,47.9 r90 bottom
TP302 "" TP_SMD_1.0mm 71.4,52.1 r90 top
TP303 "" TP_SMD_1.0mm 73.9,51.7 r90 top
TP400 "" TP_SMD_1.0mm 46.1,22.5 r90 bottom
TP401 "" TP_SMD_1.0mm 24.4,21.5 r270 top
TP402 "" TP_SMD_1.0mm 11.8,38.1 r90 bottom
TP403 "" TP_SMD_1.0mm 17.5,24.4 r90 bottom
TP404 "" TP_SMD_1.0mm 17.5,22.9 r270 bottom
TP405 "" TP_SMD_1.0mm 48.2,30.4 r90 bottom
TP406 "" TP_SMD_1.0mm 33.1,39.6 r90 bottom
TP407 "" TP_SMD_1.0mm 13.2,39.3 r90 bottom
TP408 "" TP_SMD_1.0mm 65.1,29.9 r90 bottom
TP409 "" TP_SMD_1.0mm 66.8,29.9 r90 bottom
TP410 "" TP_SMD_1.0mm 15.8,22.2 r90 bottom
TP600 "" TP_SMD_1.0mm 51.6,48.4 r0 bottom
TP601 "" TP_SMD_1.0mm 29.9,54.2 r180 bottom
TP602 "" TP_SMD_1.0mm 27.1,56.2 r270 bottom
TP700 "" TP_SMD_1.0mm 3.7,52.9 r90 bottom
TP701 "" TP_SMD_1.0mm 5.7,49.4 r0 bottom
TP702 "" TP_SMD_1.0mm 15.1,42.8 r90 bottom
TP703 "" TP_SMD_1.0mm 18.3,45.4 r90 bottom
U1 "LPC4330FET180" BGA_180_P0.80_12X12MM 38.65,70.15 r90 top locked value=LPC43S50FET180
U2 "TPS3809K33DBV" SOT23 28.5,59.5 r180 top
U3 "ATSHA204A (key)" UDFN-8 26.6,75.7 r0 top
U201 "SDRAM 8MB" BGA_54_P0.80_8X8MM 54.4,70.7 r180 top locked
U202 "S25FL064LABMFI011" SO_08_P50_R286_MIL 25.85,67.8 r90 top
U333 "LAN9354" MLF_56_P0.5_8X8MM 65.7,49.2 r180 top
U400 "TPS2372-4" QFN_20_P0.65_5X5MM_PWR 22.2,24.75 r180 top
U401 "SPBW06G-12" SPBW06_SIP8 5.9,22.5 r90 top locked
U402 "EL3H7(TA)" OPTO_SO4_1.27MM 25.6,40 r90 top
U403 "EL3H7(TA)" OPTO_SO4_1.27MM 28.9,40 r90 top
U404 "MAX15062C" TDFN_08_0.5MM_2x2MM 25.3,30.5 r90 top
U405 "EL3H7(TA)" OPTO_SO4_1.27MM 25,39.5 r90 bottom
U406 "TPS23880" QFN_56_P0.5_8X8MM_PWR 38.7,35.6 r90 top locked
U407 "EL3H7(TA)" OPTO_SO4_1.27MM 28.4,39.5 r270 bottom
U408 "Si8631AB" SO_16_P50_R210_MIL 37.545,44.467 r270 bottom
U409 "74LVC1G07DBV" SOT23-5 37.6,48 r90 top
U600 "AP65111A" SOT23-6 47.3,44.9 r0 top
U601 "AP65111A" SOT23-6 29.4,49 r90 top
U700 "WM8974" QFN_24_P0.5_4x4MM 22.3,51.9 r90 top
U701 "TS9224IPT" SSOP_14_P0.65_R6.40_MM 8.6,50.8 r270 top
U703 "G3VM-41" SO4_G3VM 8.8,45.5 r90 top value=G3VM-41DY1
V1 "BC846B" SOT23 40.8,54.4 r270 bottom
V402 "SQJ476EP" SO_08_P50_R210_MIL_POWERPAK 32.85,24.35 r90 top
V403 "SQJ476EP" SO_08_P50_R210_MIL_POWERPAK 41.8,24.323 r90 top
V700 "BC846B" SOT23 19.5,43.6 r180 bottom
X1 "1x4 pins" HEADER_1X4_MSN 24.1,79.4 r0 top
X2 "2x5 pins" HEADER_2X5_FSN_1.27MM_SMD 37.84,52 r90 bottom locked
X3 "53398-0271" 53398-0271 36.05,54.3 r0 top locked
X4 "" TP_THT_1.6mm 61.1,79.4 r0 top
X5 "" TP_THT_1.6mm 61.1,59.4 r0 top
X6 "" TP_THT_1.6mm 24.1,59.4 r0 top
X7 "" TP_THT_1.6mm 50,39.7 r0 top
X8 "" TP_THT_1.6mm 70,39.7 r0 top
X300 "NE8FAH" RJ45-NE8FAH 42.7,-1 r0 top locked
X301 "NE8FAH" RJ45-NE8FAH 66.7,-1 r0 top locked
X500 "62674-161121ALF" FFC_0.5MM_16P_SMD 49.4,52.4 r180 top locked
X700 "NC4MAH" XLR_JACK_NC4MAH 17.7,-1.1 r180 top locked

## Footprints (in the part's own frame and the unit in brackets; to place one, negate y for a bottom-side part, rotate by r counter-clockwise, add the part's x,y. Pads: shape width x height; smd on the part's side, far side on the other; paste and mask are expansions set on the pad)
53398-0271 [mm] "Molex shrouded header, 2pin, male, straight, SMD (53398 series)"
  rect 0.8x1.3 smd: 1(0,0) 2(1.25,0)
  rect 2.1x3 smd: 91(-2.55,-2.75) 92(3.8,-2.75)
  silkscreen extent -1.6,-4 2.9,-0.3, body extent -3.22,-3.7 4.43,0.5
BGA_54_P0.80_8X8MM [mm] "BGA 54 balls, 0.8mm pitch, 8x8mm package"
  round 0.4 smd paste+0 mask+0.05: A1(-3.2,3.2) A2(-2.4,3.2) A3(-1.6,3.2) A7(1.6,3.2) A8(2.4,3.2) A9(3.2,3.2) B1(-3.2,2.4) B2(-2.4,2.4) B3(-1.6,2.4) B7(1.6,2.4) B8(2.4,2.4) B9(3.2,2.4) C1(-3.2,1.6) C2(-2.4,1.6) C3(-1.6,1.6) C7(1.6,1.6) C8(2.4,1.6) C9(3.2,1.6) D1(-3.2,0.8) D2(-2.4,0.8) D3(-1.6,0.8) D7(1.6,0.8) D8(2.4,0.8) D9(3.2,0.8) E1(-3.2,0) E2(-2.4,0) E3(-1.6,0) E7(1.6,0) E8(2.4,0) E9(3.2,0) F1(-3.2,-0.8) F2(-2.4,-0.8) F3(-1.6,-0.8) F7(1.6,-0.8) F8(2.4,-0.8) F9(3.2,-0.8) G1(-3.2,-1.6) G2(-2.4,-1.6) G3(-1.6,-1.6) G7(1.6,-1.6) G8(2.4,-1.6) G9(3.2,-1.6) H1(-3.2,-2.4) H2(-2.4,-2.4) H3(-1.6,-2.4) H7(1.6,-2.4) H8(2.4,-2.4) H9(3.2,-2.4) J1(-3.2,-3.2) J2(-2.4,-3.2) J3(-1.6,-3.2) J7(1.6,-3.2) J8(2.4,-3.2) J9(3.2,-3.2)
  silkscreen extent -4.1,-4 4,4.1, body extent -4,-4 4,4, height 1.2
BGA_180_P0.80_12X12MM [mm] "BGA 180pin, 0.8mm pitch, 12x12mm housing"
  round 0.4 smd: A1(-5.2,5.2) A2(-4.4,5.2) A3(-3.6,5.2) A4(-2.8,5.2) A5(-2,5.2) A6(-1.2,5.2) A7(-0.4,5.2) A8(0.4,5.2) A9(1.2,5.2) A10(2,5.2) A11(2.8,5.2) A12(3.6,5.2) A13(4.4,5.2) A14(5.2,5.2) B1(-5.2,4.4) B2(-4.4,4.4) B3(-3.6,4.4) B4(-2.8,4.4) B5(-2,4.4) B6(-1.2,4.4) B7(-0.4,4.4) B8(0.4,4.4) B9(1.2,4.4) B10(2,4.4) B11(2.8,4.4) B12(3.6,4.4) B13(4.4,4.4) B14(5.2,4.4) C1(-5.2,3.6) C2(-4.4,3.6) C3(-3.6,3.6) C4(-2.8,3.6) C5(-2,3.6) C6(-1.2,3.6) C7(-0.4,3.6) C8(0.4,3.6) C9(1.2,3.6) C10(2,3.6) C11(2.8,3.6) C12(3.6,3.6) C13(4.4,3.6) C14(5.2,3.6) D1(-5.2,2.8) D2(-4.4,2.8) D3(-3.6,2.8) D4(-2.8,2.8) D5(-2,2.8) D6(-1.2,2.8) D7(-0.4,2.8) D8(0.4,2.8) D9(1.2,2.8) D10(2,2.8) D11(2.8,2.8) D12(3.6,2.8) D13(4.4,2.8) D14(5.2,2.8) E1(-5.2,2) E2(-4.4,2) E3(-3.6,2) E4(-2.8,2) E5(-2,2) E6(-1.2,2) E7(-0.4,2) E8(0.4,2) E9(1.2,2) E10(2,2) E11(2.8,2) E12(3.6,2) E13(4.4,2) E14(5.2,2) F1(-5.2,1.2) F2(-4.4,1.2) F3(-3.6,1.2) F4(-2.8,1.2) F5(-2,1.2) F10(2,1.2) F11(2.8,1.2) F12(3.6,1.2) F13(4.4,1.2) F14(5.2,1.2) G1(-5.2,0.4) G2(-4.4,0.4) G3(-3.6,0.4) G4(-2.8,0.4) G5(-2,0.4) G10(2,0.4) G11(2.8,0.4) G12(3.6,0.4) G13(4.4,0.4) G14(5.2,0.4) H1(-5.2,-0.4) H2(-4.4,-0.4) H3(-3.6,-0.4) H4(-2.8,-0.4) H5(-2,-0.4) H10(2,-0.4) H11(2.8,-0.4) H12(3.6,-0.4) H13(4.4,-0.4) H14(5.2,-0.4) J1(-5.2,-1.2) J2(-4.4,-1.2) J3(-3.6,-1.2) J4(-2.8,-1.2) J5(-2,-1.2) J10(2,-1.2) J11(2.8,-1.2) J12(3.6,-1.2) J13(4.4,-1.2) J14(5.2,-1.2) K1(-5.2,-2) K2(-4.4,-2) K3(-3.6,-2) K4(-2.8,-2) K5(-2,-2) K6(-1.2,-2) K7(-0.4,-2) K8(0.4,-2) K9(1.2,-2) K10(2,-2) K11(2.8,-2) K12(3.6,-2) K13(4.4,-2) K14(5.2,-2) L1(-5.2,-2.8) L2(-4.4,-2.8) L3(-3.6,-2.8) L4(-2.8,-2.8) L5(-2,-2.8) L6(-1.2,-2.8) L7(-0.4,-2.8) L8(0.4,-2.8) L9(1.2,-2.8) L10(2,-2.8) L11(2.8,-2.8) L12(3.6,-2.8) L13(4.4,-2.8) L14(5.2,-2.8) M1(-5.2,-3.6) M2(-4.4,-3.6) M3(-3.6,-3.6) M4(-2.8,-3.6) M5(-2,-3.6) M6(-1.2,-3.6) M7(-0.4,-3.6) M8(0.4,-3.6) M9(1.2,-3.6) M10(2,-3.6) M11(2.8,-3.6) M12(3.6,-3.6) M13(4.4,-3.6) M14(5.2,-3.6) N1(-5.2,-4.4) N2(-4.4,-4.4) N3(-3.6,-4.4) N4(-2.8,-4.4) N5(-2,-4.4) N6(-1.2,-4.4) N7(-0.4,-4.4) N8(0.4,-4.4) N9(1.2,-4.4) N10(2,-4.4) N11(2.8,-4.4) N12(3.6,-4.4) N13(4.4,-4.4) N14(5.2,-4.4) P1(-5.2,-5.2) P2(-4.4,-5.2) P3(-3.6,-5.2) P4(-2.8,-5.2) P5(-2,-5.2) P6(-1.2,-5.2) P7(-0.4,-5.2) P8(0.4,-5.2) P9(1.2,-5.2) P10(2,-5.2) P11(2.8,-5.2) P12(3.6,-5.2) P13(4.4,-5.2) P14(5.2,-5.2)
  silkscreen extent -6.7,-6.3 6.2,6.64, body extent -6,-6 6,6, height 0.94
C0402 [mm]
  rrect25% 0.6x0.6 smd: 1(-0.5,0) 2(0.5,0)
  silkscreen extent -0.1,-0.22 0.1,0.22, body extent -0.5,-0.25 0.5,0.25, height 0.5
C0603 [mm]
  rrect25% 1x1 smd: 1(-0.8,0) 2(0.8,0)
  silkscreen extent -0.15,-0.35 0.15,0.35, body extent -0.8,-0.4 0.8,0.4, height 0.8
C0805 [mm]
  rrect25% 1.1x1.5 smd: 1(-0.95,0) 2(0.95,0)
  silkscreen extent -0.2,-0.57 0.2,0.58, body extent -1,-0.63 1,0.63, height 1.25
C1206 [mil]
  rrect25% 44x67 smd: 1(-57,0) 2(57,0)
  silkscreen extent -31,-30 29,32, body extent -60,-25 65,25, height 49
C1210 [mm]
  rrect25% 1.3x2.7 smd: 1(-1.45,0) 2(1.45,0)
  silkscreen extent -0.4,-1.2 0.4,1.2, body extent -1.6,-1.25 1.6,1.25, height 2
C1812 [mm]
  rect 1.2x3.3 smd: 1(-2.3,0) 2(2.3,0)
  silkscreen extent -0.85,-1.73 0.83,1.73, body extent -2.37,-1.6 2.37,1.6, height 1.6
DO214AC [mm]
  rrect50% 2.35x1.6 smd: A(1.925,0) C(-1.925,0)
  silkscreen extent -2.3,-1.35 2.3,1.35, body extent -2.5,-1.35 2.5,1.35, height 2.52
FFC_0.5MM_16P_SMD [mm] "FFC, 1x16pin, 0.5mm pitch, vertical, SMD (Amphenol 62674)"
  rect 0.4x1.6 smd: 1(3.75,1.2) 2(3.25,-1.2) 3(2.75,1.2) 4(2.25,-1.2) 5(1.75,1.2) 6(1.25,-1.2) 7(0.75,1.2) 8(0.25,-1.2) 9(-0.25,1.2) 10(-0.75,-1.2) 11(-1.25,1.2) 12(-1.75,-1.2) 13(-2.25,1.2) 14(-2.75,-1.2) 15(-3.25,1.2) 16(-3.75,-1.2)
  rect 0.6x1.6 smd: 91(4.75,1.2) 92(4.75,-1.2) 93(-4.75,1.2) 94(-4.75,-1.2)
  silkscreen extent -6.4,-1.8 6.4,2.64, body extent -6.25,-1.75 6.25,1.65, height 4.08
FIDUCIAL_1MM [mm] "Fiducial, 1mm dot with 2mm ring"
  round 1 smd mask+0.5: 1(0,0)
  Top Layer keep-out circle w0.1: c0,0 r1
HEADER_1X4_MSN [mil] "Pin Header, 1x4pin, male, straight, no-lock"
  rect 63x63 hole 40: 1(0,0)
  round 63 hole 40: 2(100,0) 3(200,0) 4(300,0)
  silkscreen extent -83,-50 350,50, body extent -42,-45 342,47, height 320
HEADER_2X5_FSN_1.27MM_SMD [mm] "Socket 1.27mm pitch, 3mm pins, female, straight, no-lock, SMD"
  rect 2.25x0.74 smd: 1(0,0) 2(3.65,0) 3(0,-1.27) 4(3.65,-1.27) 5(0,-2.54) 6(3.65,-2.54) 7(0,-3.81) 8(3.65,-3.81) 9(0,-5.08) 10(3.65,-5.08)
  silkscreen extent -1.63,-5.9 4.75,0.83, body extent -0.9,-5.73 4.6,0.62, height 4.5
L0603 [mm]
  rrect25% 1x1 smd: 1(-0.8,0) 2(0.8,0)
  silkscreen extent -0.15,-0.35 0.15,0.35, body extent -0.8,-0.4 0.8,0.4, height 1
L0805 [mm]
  rrect25% 1.2x1.4 smd: 1(-1,0) 2(1,0)
  silkscreen extent -0.2,-0.57 0.2,0.58, body extent -1,-0.63 1,0.63, height 1.1
L_NR3015 [mm] "Inductor shielded, SMD, 3x3mm"
  rrect25% 0.8x2.7 smd: 1(-1.1,0) 2(1.1,0)
  body extent -1.5,-1.5 1.5,1.5, height 1
L_NR4018 [mm] "Inductor shielded, SMD, 4x4mm"
  rrect25% 1.2x3.7 smd: 1(-1.4,0) 2(1.4,0)
  body extent -2,-2 2.1,2, height 1.8
L_NR6028 [mm] "Inductor shielded, SMD, 6x6mm"
  rrect25% 1.6x5.7 smd: 1(-2.35,0) 2(2.35,0)
  body extent -3.1,-3 3.2,3, height 2.8
MLF_56_P0.5_8X8MM [mm] "Quad Flat No-Lead, 56pin, 0.5 mm pitch"
  oval 0.8x0.25 smd: 1(-4,3.25) 2(-4,2.75) 3(-4,2.25) 4(-4,1.75) 5(-4,1.25) 6(-4,0.75) 7(-4,0.25) 8(-4,-0.25) 9(-4,-0.75) 10(-4,-1.25) 11(-4,-1.75) 12(-4,-2.25) 13(-4,-2.75) 14(-4,-3.25) 29(4,-3.25) 30(4,-2.75) 31(4,-2.25) 32(4,-1.75) 33(4,-1.25) 34(4,-0.75) 35(4,-0.25) 36(4,0.25) 37(4,0.75) 38(4,1.25) 39(4,1.75) 40(4,2.25) 41(4,2.75) 42(4,3.25)
  oval 0.25x0.8 smd: 15(-3.25,-4) 16(-2.75,-4) 17(-2.25,-4) 18(-1.75,-4) 19(-1.25,-4) 20(-0.75,-4) 21(-0.25,-4) 22(0.25,-4) 23(0.75,-4) 24(1.25,-4) 25(1.75,-4) 26(2.25,-4) 27(2.75,-4) 28(3.25,-4) 43(3.25,4) 44(2.75,4) 45(2.25,4) 46(1.75,4) 47(1.25,4) 48(0.75,4) 49(0.25,4) 50(-0.25,4) 51(-0.75,4) 52(-1.25,4) 53(-1.75,4) 54(-2.25,4) 55(-2.75,4) 56(-3.25,4)
  rect 6.2x6.2 smd: 57(0,0)
  silkscreen extent -5.05,-4.15 4.15,4.15, body extent -4.05,-4.05 4.05,4.05, height 0.95
OPTO_SO4_1.27MM [mm] "SMD, half pitch 1.27mm, 4 pin"
  rect 1.5x0.9 smd: 1(-3.3,0.635) 2(-3.3,-0.635) 3(3.3,-0.635) 4(3.3,0.635)
  silkscreen extent -2.5,-1.6 2.5,1.6, body extent -3.5,-1.3 3.5,1.3, height 2.01
PD70224 [mm] "Dual MOSFET Bridge Rectifier, 6x8mm, MLPQ-40L"
  oct 0.75x0.28 smd: 1(-2.85,2.75) 2(-2.85,2.25) 3(-2.85,1.75) 5(-2.85,0.75) 6(-2.85,0.25) 7(-2.85,-0.25) 8(-2.85,-0.75) 10(-2.85,-1.75) 11(-2.85,-2.25) 12(-2.85,-2.75) 21(2.85,-2.75) 22(2.85,-2.25) 23(2.85,-1.75) 25(2.85,-0.75) 26(2.85,-0.25) 27(2.85,0.25) 28(2.85,0.75) 30(2.85,1.75) 31(2.85,2.25) 32(2.85,2.75)
  oct 0.28x0.75 smd: 13(-1.75,-3.855) 14(-1.25,-3.855) 16(-0.25,-3.855) 17(0.25,-3.855) 19(1.25,-3.855) 20(1.75,-3.855) 33(1.75,3.855) 34(1.25,3.855) 36(0.25,3.855) 37(-0.25,3.855) 39(-1.25,3.855) 40(-1.75,3.855)
  rect 4.37x2.29 smd: 41(0,2.06)
  rect 4.37x3.56 smd: 42(0,-1.425)
  silkscreen extent -3.74,-4.2 3.2,4.2, body extent -3,-4 3,4, height 0.92
Q_4PIN_3225 [mm] "Quarz SMD 4pin 3.2x2.5mm"
  rrect25% 1.4x1.2 smd: 1(-1.1,-0.85) 2(1.1,-0.85) 3(1.1,0.85) 4(-1.1,0.85)
  body extent -1.6,-1.25 1.6,1.25, height 1.01
QFN_20_P0.65_5X5MM_PWR [mm] "QFN, 20-Leads, Body 5x5mm, Pitch 0.65mm, Thermal Pad 3.15x3.15mm (TI RGW20)"
  oval 0.8x0.32 smd: 1(-2.3,1.3) 2(-2.3,0.65) 3(-2.3,0) 4(-2.3,-0.65) 5(-2.3,-1.3) 11(2.3,-1.3) 12(2.3,-0.65) 13(2.3,0) 14(2.3,0.65) 15(2.3,1.3)
  oval 0.32x0.8 smd: 6(-1.3,-2.3) 7(-0.65,-2.3) 8(0,-2.3) 9(0.65,-2.3) 10(1.3,-2.3) 16(1.3,2.3) 17(0.65,2.3) 18(0,2.3) 19(-0.65,2.3) 20(-1.3,2.3)
  rect 2.2x2.2 smd: 21(0,0)
  silkscreen extent -3.38,-2.73 2.73,2.73, body extent -2.5,-2.5 2.5,2.5, height 0.97
QFN_24_P0.5_4x4MM [mm] "QFN 24pin, pitch 0.5mm, body 4x4mm"
  oval 0.8x0.25 smd: 1(-2,1.25) 2(-2,0.75) 3(-2,0.25) 4(-2,-0.25) 5(-2,-0.75) 6(-2,-1.25) 13(2,-1.25) 14(2,-0.75) 15(2,-0.25) 16(2,0.25) 17(2,0.75) 18(2,1.25)
  oval 0.25x0.8 smd: 7(-1.25,-2) 8(-0.75,-2) 9(-0.25,-2) 10(0.25,-2) 11(0.75,-2) 12(1.25,-2) 19(1.25,2) 20(0.75,2) 21(0.25,2) 22(-0.25,2) 23(-0.75,2) 24(-1.25,2)
  rect 2.6x2.6 smd: 25(0,0)
  silkscreen extent -2.79,-2.1 2.1,2.1, body extent -2,-2 2,2, height 1.05
QFN_56_P0.5_8X8MM_PWR [mm] "Quad Flat No-Lead, 56pin, 0.5 mm pitch, 8x8mm (TI RTQ)"
  oval 0.9x0.28 smd: 1(-4,3.25) 2(-4,2.75) 3(-4,2.25) 4(-4,1.75) 5(-4,1.25) 6(-4,0.75) 7(-4,0.25) 8(-4,-0.25) 9(-4,-0.75) 10(-4,-1.25) 11(-4,-1.75) 12(-4,-2.25) 13(-4,-2.75) 14(-4,-3.25) 29(4,-3.25) 30(4,-2.75) 31(4,-2.25) 32(4,-1.75) 33(4,-1.25) 34(4,-0.75) 35(4,-0.25) 36(4,0.25) 37(4,0.75) 38(4,1.25) 39(4,1.75) 40(4,2.25) 41(4,2.75) 42(4,3.25)
  oval 0.28x0.9 smd: 15(-3.25,-4) 16(-2.75,-4) 17(-2.25,-4) 18(-1.75,-4) 19(-1.25,-4) 20(-0.75,-4) 21(-0.25,-4) 22(0.25,-4) 23(0.75,-4) 24(1.25,-4) 25(1.75,-4) 26(2.25,-4) 27(2.75,-4) 28(3.25,-4) 43(3.25,4) 44(2.75,4) 45(2.25,4) 46(1.75,4) 47(1.25,4) 48(0.75,4) 49(0.25,4) 50(-0.25,4) 51(-0.75,4) 52(-1.25,4) 53(-1.75,4) 54(-2.25,4) 55(-2.75,4) 56(-3.25,4)
  rect 5.7x5.7 smd: 57(0,0)
  silkscreen extent -4.72,-4.15 4.15,4.15, body extent -4,-4 4,4, height 1
R0402 [mm]
  rrect25% 0.6x0.6 smd: 1(-0.5,0) 2(0.5,0)
  silkscreen extent -0.1,-0.2 0.1,0.2, body extent -0.5,-0.25 0.5,0.25, height 0.4
R0603 [mm]
  rrect25% 1x1 smd: 1(-0.8,0) 2(0.8,0)
  silkscreen extent -0.2,-0.35 0.2,0.35, body extent -0.8,-0.4 0.8,0.4, height 0.6
R0805 [mil]
  rect 50x55 smd: 1(-42.5,0) 2(42.5,0)
  silkscreen extent -13,-24 13,26, body extent -48,-19 53,23, height 24
R_0402X8_CONCAVE [mm] "Chip resistor array, 4 x 0402"
  rrect25% 0.4x0.5 smd paste-0.025 mask+0.05: 1(-0.8,-0.5) 4(0.8,-0.5) 5(0.8,0.5) 8(-0.8,0.5)
  rrect25% 0.3x0.5 smd paste-0.025 mask+0.05: 2(-0.25,-0.5) 3(0.25,-0.5) 6(0.25,0.5) 7(-0.25,0.5)
  silkscreen extent -1,-0.05 1,0.05, body extent -1,-0.5 1,0.5, height 0.4
RJ45-NE8FAH [mm] "RJ45 connector, 8pin, no LEDs, Push lock"
  rect 1.5x1.5 hole 0.9: 1(-4.45,14.61)
  round 1.5 hole 0.9: 2(-3.18,17.15) 3(-1.91,14.61) 4(-0.64,17.15) 5(0.63,14.61) 6(1.9,17.15) 7(3.17,14.61) 8(4.44,17.15)
  round 1.7 hole 0.9: 9(-6.595,13.34)
  round 1 hole 1.6 unplated: MH1(5.08,12.7) MH2(-5.08,3.81)
  silkscreen extent -12.4,0 12.4,21.5, body extent -12.5,-6.8 12.5,21.5, height 29.11
SC74-6-2 [mm] "6pin SMD package, 2.9x2.5mm"
  rect 0.6x0.5 smd: 1(-1.2,0.95) 2(-1.2,0) 3(-1.2,-0.95) 4(1.2,-0.95) 5(1.2,0) 6(1.2,0.95)
  silkscreen extent -1.83,-1.5 0.6,1.72, body extent -1.38,-1.5 1.39,1.5, height 0.94
SO4_G3VM [mm] "SMD 4pin 2.54mm pitch, 7.62mm wide"
  rrect50% 1.5x1.6 smd: 1(-1.27,-4.2) 2(1.27,-4.2) 3(1.27,4.2) 4(-1.27,4.2)
  silkscreen extent -2.9,-4.6 2.4,3, body extent -2.29,-5 2.29,5, height 3.7
SO_08_P50_R210_MIL_POWERPAK [mm] "SO 8-lead, 50mil pitch, 4.0x5.0 body, PowerPAK, SMD"
  rect 1.27x0.61 smd: 1(-2.667,1.905) 2(-2.667,0.635) 3(-2.667,-0.635) 4(-2.667,-1.905) 5(2.667,-1.905) 6(2.667,-0.635) 7(2.667,0.635) 8(2.667,1.905)
  rect 3.6x3.9 smd: 9(0.55,0)
  silkscreen extent -2.44,-2.5 1.75,2.94, body extent -3.07,-2.57 3.08,2.58, height 1.04
SO_08_P50_R286_MIL [mil]
  oval 63x25 smd: 1(-143,75) 2(-143,25) 3(-143,-25) 4(-143,-75) 5(143,-75) 6(143,-25) 7(143,25) 8(143,75)
  silkscreen extent -151,101 -133,119, body extent -160,-107 159,107, height 67
SO_16_P50_R210_MIL [mil]
  oval 63x25 smd: 1(-105,175) 2(-105,125) 3(-105,75) 4(-105,25) 5(-105,-25) 6(-105,-75) 7(-105,-125) 8(-105,-175) 9(105,-175) 10(105,-125) 11(105,-75) 12(105,-25) 13(105,25) 14(105,75) 15(105,125) 16(105,175)
  silkscreen extent -69,-212 69,212, body extent -122,-198 122,196, height 69
SOD323 [mm] "SOD, 2-Leads, Body 1.7x1.25mm"
  rect 0.63x0.83 smd: A(1.115,0) C(-1.115,0)
  silkscreen extent -1.22,-0.85 0.7,0.92, body extent -1.3,-0.68 1.3,0.67, height 1.1
SOT23 [mm]
  rrect50% 0.6x1.1 smd: 1(-0.95,-1) 2(0.95,-1) 3(0,1)
  silkscreen extent -1.5,-0.64 1.5,0.6, body extent -1.5,-1.25 1.5,1.25, height 1.23
SOT23-5 [mm] "SOT23, 5-lead, 3 x 1.7mm body"
  rrect50% 0.6x1.1 smd: 1(-0.95,-1.3) 2(0,-1.3) 3(0.95,-1.3) 4(0.95,1.3) 5(-0.95,1.3)
  silkscreen extent -1.8,-1.3 1.5,0.7, body extent -1.45,-1.4 1.45,1.4, height 1.45
SOT23-6 [mm]
  rect 0.65x1.1 smd: 1(-0.953,-1.397)
  oval 0.65x1.1 smd: 2(0,-1.397) 3(0.953,-1.397) 4(0.953,1.397) 5(0,1.397) 6(-0.953,1.397)
  silkscreen extent -1.5,-0.74 1.5,0.74, body extent -1.45,-1.4 1.45,1.4, height 1.45
SPBW06_SIP8 [mm] "DC/DC Module (Mean Well), SIP-8"
  rect 1.6x1.6 hole 0.8: 1(0,0)
  round 1.6 hole 0.8: 2(2.5,0) 3(5,0) 5(10,0) 6(12.5,0) 7(15,0) 8(17.5,0)
  silkscreen extent -2.1,-5.8 19.9,3.6, body extent -2,-5.7 19.8,3.5, height 11.12
SSOP_14_P0.65_R6.40_MM [mm] "SSOP 14pin, 0.65mm pitch, 4.4x5.0mm body"
  oval 0.38x1.4 smd paste+0 mask+0.075: 1(-2.275,-3) 2(-1.625,-3) 3(-0.975,-3) 4(-0.325,-3) 5(0.325,-3) 6(0.975,-3) 7(1.625,-3) 8(1.625,3) 9(0.975,3) 10(0.325,3) 11(-0.325,3) 12(-0.975,3) 13(-1.625,3) 14(-2.275,3)
  silkscreen extent -3.1,-2.9 2.06,2.2, body extent -2.83,-3.23 2.17,3.17, height 1.1
T_ETH_18.3x16.0MM [mm] "Transformer, Ethernet 1000BT, SMD (Wuerth 7990220122)"
  rect 0.76x2.3 smd: 1(-6.985,-7.24) 2(-5.715,-7.24) 3(-4.445,-7.24) 4(-3.175,-7.24) 5(-1.905,-7.24) 6(-0.635,-7.24) 7(0.635,-7.24) 8(1.905,-7.24) 9(3.175,-7.24) 10(4.445,-7.24) 11(5.715,-7.24) 12(6.985,-7.24) 13(6.985,7.24) 14(5.715,7.24) 15(4.445,7.24) 16(3.175,7.24) 17(1.905,7.24) 18(0.635,7.24) 19(-0.635,7.24) 20(-1.905,7.24) 21(-3.175,7.24) 22(-4.445,7.24) 23(-5.715,7.24) 24(-6.985,7.24)
  silkscreen extent -9.4,-8.52 9.4,7.6, body extent -9.14,-8 9.15,8, height 9.05
TDFN_08_0.5MM_2x2MM [mm] "TDFN, 8 pins, Body 2x2mm, Pitch 0.5mm"
  rect 0.85x0.3 smd: 1(-0.85,0.75) 2(-0.85,0.25) 3(-0.85,-0.25) 4(-0.85,-0.75) 5(0.85,-0.75) 6(0.85,-0.25) 7(0.85,0.25) 8(0.85,0.75)
  silkscreen extent -1.55,-1.2 1,1.25, body extent -1,-1 1,1, height 0.76
TP_SMD_1.0mm [mil] "Testpoint, no via, 1.0mm"
  round 40 smd paste-3937.01: 1(0,0)
TP_THT_1.6mm [mm] "Testpoint 1.6mm, drill 1.016mm"
  round 1.2 smd paste-100: 1(0,0)
  silkscreen extent -0.9,-0.9 0.9,0.9
UDFN-8 [mm] "UDFN, 8 pins, Body 2x3mm, Pitch 0.5mm, MO-229"
  rect 0.75x0.3 smd: 1(-1.5,0.75) 2(-1.5,0.25) 3(-1.5,-0.25) 4(-1.5,-0.75) 5(1.5,-0.75) 6(1.5,-0.25) 7(1.5,0.25) 8(1.5,0.75)
  rect 1.36x1.46 smd: 9(0,0)
  silkscreen extent -1.55,1.15 -1.45,1.25, body extent -1.52,-1.02 1.52,1.02, height 0.8
XLR_JACK_NC4MAH [mm] "XLR, male, 4pin, no switches, NC4MAH"
  round 2.3 hole 1.6: 1(6.98,-17.78) 4(-6.98,-17.78) 98(3.81,-8.89) 99(-3.81,-3.81)
  round 2 hole 1.2: 2(3.81,-12.7) 3(-3.81,-12.7) G(0,-12.7)
  silkscreen extent -12.6,-19.2 12.9,0, body extent -12.5,-19 12.85,2.7, height 25.35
